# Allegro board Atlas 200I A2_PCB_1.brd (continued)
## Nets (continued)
GND: C4.2 C5.2 C7.2 C8.2 C9.1 C10.1 C11.1 C12.1 C13.1 C14.1 C15.1 C16.1 C17.1 C18.1 C19.2 C20.1 C23.2 C24.2 C27.2 C28.2 C29.2 C30.2 C31.2 C32.1 C33.2 C34.2 C35.2 C36.1 C37.1 C38.1 C39.1 C40.1 C43.1 C44.2 C45.1 C46.2 C47.1 C48.1 C49.1 C50.1 C51.1 C52.1 C53.1 C54.1 C55.1 C56.1 C57.1 C58.1 C59.1 C60.1 C61.1 C62.1 C63.1 C64.2 C65.1 C66.1 C67.1 C68.1 C69.1 C70.1 C71.1 C72.1 C73.1 C74.1 C75.1 C76.1 C77.1 C78.1 C79.1 C80.1 C81.1 C82.1 C85.2 C86.1 C87.1 C88.2 C90.2 C92.2 C93.2 C94.1 C95.2 C98.1 C99.1 C100.1 C101.1 C102.1 C103.1 C104.2 C109.2 C113.1 C115.1 C116.1 C117.1 C118.2 C119.2 C120.1 C121.2 C122.2 C123.1 C124.1 C125.1 C126.1 C127.2 C128.2 C129.1 C130.1 C131.2 C132.2 C133.2 C134.2 C135.2 C136.1 C137.2 C138.1 C139.1 C140.1 C141.2 C142.2 C143.2 C144.2 C145.2 C146.2 C150.2 C151.2 C152.2 C153.2 C154.2 C155.2 C156.2 C157.2 C158.2 C159.2 C160.2 C161.2 C162.2 C163.2 C164.2 C165.2 C166.2 C167.2 C174.2 C175.1 C176.1 C177.1 C178.2 C179.1 C180.2 C181.2 C182.2 C183.2 C184.2 C185.1 C186.1 C187.1 C188.1 C189.2 C190.2 C191.2 C192.2 C193.1 C194.1 C195.1 C196.1 C197.2 C198.2 C199.2 C200.2 C201.2 C202.2 C203.2 C204.2 C205.2 C206.2 C207.2 C208.2 C209.1 C210.1 C212.2 C214.1 C215.2 C216.2 C217.2 C219.2 C220.2 C221.2 C222.1 C223.1 C224.1 C225.1 C227.2 C228.1 C229.1 C230.1 C231.1 C232.1 C233.2 C234.2 C235.2 C236.2 C237.2 C238.2 C241.2 C242.2 C243.2 C244.2 C245.2 C246.2 C247.2 C248.2 C249.2 C252.2 C253.2 C254.2 C255.2 C256.2 C257.2 C258.2 C259.2 C260.2 C261.2 C262.2 C263.2 C264.2 C265.2 C266.2 C267.2 C268.2 C270.2 C271.2 C272.2 C273.2 C274.2 C275.2 C276.2 C277.2 C278.2 C279.2 C280.2 C281.2 C282.2 C283.2 C284.2 C285.1 C286.1 C287.1 C288.2 C289.2 C290.2 C291.2 C292.1 C293.2 C294.2 C295.2 C296.2 C297.2 C298.2 C299.2 C300.1 C301.1 C302.2 C303.1 C304.2 C305.2 C306.2 C307.2 C311.1 C312.2 C313.1 C314.2 C317.2 C318.2 C321.1 C322.1 C323.2 C324.1 C325.1 C326.1 C327.1 C328.2 C329.2 C330.2 C331.2 C332.1 C333.2 C334.2 C335.2 C336.2 C337.2 C338.2 C339.2 C340.2 C341.1 C342.1 C343.2 C344.2 C345.2 C346.1 C347.1 C348.2 C349.2 C350.2 C351.2 C352.2 C353.1 C354.1 C355.1 C356.1 C357.1 C358.1 C359.1 C360.2 C361.2 C362.2 C363.2 C364.1 C365.1 C366.1 C367.2 C368.2 C369.2 C370.2 D2.3 D4.3 D4.8 D5.2 D6.3 D6.8 D9.3 D9.8 D10.3 D10.8 D13.3 D13.8 D15.3 D15.8 D21.3 D21.8 D23.3 D23.8 D30.2 D41.2 F1.1 J1.1 J1.3 J1.9 J1.15 J1.21 J1.27 J1.33 J1.39 J1.45 J1.51 J1.57 J1.71 J1.73 J1.75 J1.76 J1.77 J2.1 J2.7 J2.18 J2.33 J2.39 J2.45 J2.51 J2.57 J2.63 J2.69 J2.75 J2.76 J2.77 J3.6 J3.10 J3.11 J3.12 J3.13 J3.14 J4.1 J4.12 J4.13 J4.24 J4.25 J4.26 J4.27 J4.28 J5.4 J5.7 J5.13 J5.16 J5.19 J5.20 J5.21 J5.22 J6.2 J6.5 J6.8 J6.11 J6.17 J6.20 J6.21 J6.22 J6.23 J7.2 J7.5 J7.8 J7.11 J7.17 J7.20 J7.21 J7.22 J7.23 J8.4 J9.2 J9.3 J10.8 J10.11 J10.14 J10.17 J10.20 J10.23 J10.26 J10.29 J10.32 J10.35 J10.38 J10.41 J10.44 J11.6 J11.9 J11.14 J11.20 J11.25 J11.30 J11.34 J11.39 J16.1 J16.7 J16.12 J16.13 J16.19 J16.25 J16.30 J16.31 J16.36 J16.37 J16.42 J16.43 J16.48 J16.49 J16.54 J16.55 J16.60 J16.61 J16.66 J16.67 J16.72 J16.73 J16.78 J16.79 J16.84 J16.85 J16.90 J16.91 J16.96 J16.97 J16.102 J16.103 J16.108 J16.109 J16.140 J16.151 J16.154 J16.168 J16.171 J16.176 J16.183 J16.190 J16.195 J16.204 J16.210 J16.216 J16.222 J16.223 J16.228 J16.234 J16.240 J16.241 J16.246 J16.252 J16.253 J16.258 J16.264 J16.265 J16.266 J16.267 J16.268 J16.269 J16.270 J16.271 J16.285 J16.298 J16.308 J16.311 J16.322 J16.323 J17.17 J17.25 J17.26 J17.27 J17.28 M1.1 M2.1 M3.1 M4.1 M5.1 M6.1 M7.1 M8.1 M10.1 M11.1 M12.1 OSC1.2 Q1.2 Q4.2 Q5.2 Q6.2 Q8.2 Q10.2 Q12.2 Q13.2 Q14.2 Q15.2 Q16.2 R8.2 R9.2 R10.1 R17.1 R18.1 R25.2 R26.2 R27.2 R28.2 R35.1 R89.2 R91.1 R100.2 R102.2 R103.2 R104.2 R114.1 R117.2 R120.2 R121.2 R122.2 R123.2 R125.2 R127.2 R138.2 R139.2 R140.2 R141.2 R143.2 R144.2 R145.2 R146.2 R164.2 R165.2 R166.2 R167.2 R169.1 R170.1 R173.1 R176.2 R177.2 R178.2 R179.2 R180.2 R181.2 R193.2 R195.2 R200.1 R201.1 R213.1 R216.2 R217.1 R222.2 R223.2 R235.1 R241.2 R242.1 R243.2 R246.1 R248.1 R250.1 R257.2 R272.2 R275.2 R278.1 R279.1 R287.1 R305.1 R307.1 R309.2 R315.1 R317.2 R318.2 R319.1 R320.1 R321.1 R329.2 R330.2 R333.2 R334.2 R335.2 R336.2 R337.2 R338.2 R341.1 R345.1 R348.1 R350.2 R352.1 R358.1 R369.2 R375.2 R376.1 R377.1 R379.1 R383.2 R387.1 R390.1 R393.1 R395.2 R398.1 R400.1 R402.2 R403.2 R405.1 R408.2 R409.2 R412.2 R413.1 R417.1 R420.2 R421.1 R459.1 R470.2 R471.2 R472.2 R486.2 R487.2 R488.2 R516.1 R517.1 R518.1 R519.1 R520.1 R521.1 R522.1 R523.1 R524.1 R525.1 R526.1 R527.1 R528.1 R529.1 R530.1 R531.1 R535.1 R536.1 R537.1 R548.1 R554.1 R573.1 R574.2 R631.2 R633.1 R650.1 S1.3 S1.4 S1.5 S2.3 S2.4 S2.5 S3.3 S3.4 S3.5 TP8.1 TP9.1 U1.49 U2.49 U3.2 U4.2 U5.5 U5.11 U5.20 U5.21 U6.2 U7.4 U8.5 U8.7 U9.5 U9.7 U10.13 U10.18 U10.24 U10.37 U10.43 U10.48 U10.49 U11.2 U12.5 U13.2 U13.3 U13.15 U14.3 U15.8 U15.18 U15.21 U16.2 U17.4 U17.9 U18.4 U19.12 U20.7 U21.7 U22.4 U23.4 U24.7 U25.7 U27.A6 U27.C4 U27.D3 U27.E7 U27.G5 U27.H10 U27.J5 U27.K8 U27.N1 U27.N2 U27.N5 U27.P4 U27.P6 U28.2 U29.2 U30.5 U31.2 U32.7 U33.7 U34.7 U35.7 U36.51 U36.61 U36.77 U37.4 U38.77 VCXO1.2 X1.2 X1.4 X2.2 X2.4 X3.2 X3.4 X4.2 X4.4
VBUS_USB_TYPEC: J4.4 J4.9 J4.16 J4.21 LB7.1 U6.5
/CLKREQ_M2: J1.52 R26.1 R34.1
/CLKREQ_WIFI: J16.319 R42.2 R70.1
/EMMC_RESET: J16.203 R77.1 R79.1 R202.2
/EMMC_RESET_R: C87.2 R77.2 U27.K5
/LED_PHY0_ACT: R98.2 R140.1 R365.2 U1.37
/LED_PHY0_LINK: R99.2 R138.1 R366.2 U1.35
/LED_PHY1_ACT: R146.1 R154.2 R367.2 U2.37
/LED_PHY1_LINK: R144.1 R155.2 R368.2 U2.35
/OC0_USB30_REAR_1: R545.1 R598.1 U38.25
/OC0_USB30_REAR_2: R645.1 R646.1 U38.18
/OC1_USB30_REAR_1: R544.1 R546.2 U36.67
/OC1_USB30_REAR_2: R643.2 R644.1 U36.10
/OC_USB30_REAR_1: R544.2 R545.2 R647.1 U8.3
/OC_USB30_REAR_2: R644.2 R645.2 R648.1 U9.3
/PERST_M2: J16.296 R12.2 R678.1
/PERST_M2_R: C34.1 R23.2 R27.1 R32.1 U21.13
/PERST_WIFI: J16.294 R566.2 R626.1
/PERST_WIFI_R: J2.52 R39.1 R618.2
/PEWAKE_M2: J1.54 R28.1 R33.1
/PEWAKE_WIFI: J16.317 R571.2 R625.1
/PEWAKE_WIFI_R: R41.2 R43.1 R617.2
/RST_USB_HUB_R: C367.1 R632.2 R633.2 R639.2 U38.24
/SDIO_RESET_R: J2.23 R79.2
/SDIO_WAKE_R: J2.21 J16.121 R80.2
/WAKE_PHY0: J16.141 R217.2 R569.2 R624.1
/WAKE_PHY0_R: R101.1 R124.2 R125.1 R616.2
/WAKE_PHY1: J16.321 R235.2 R565.2 R621.1
/WAKE_PHY1_R: R168.1 R192.2 R193.1 R613.2
/WAKE_UART3: R44.2 R48.1
AC_IN_L: C149.1 J16.306 LB12.2
AC_IN_R: C148.1 J16.304 LB11.2
AC_MICBIAS0: J16.300 R314.2
BOARD_ID0: R507.1 R523.2 U19.4
BOARD_ID1: R506.1 R522.2 U19.5
BOARD_ID2: R505.1 R521.2 U19.6
BOARD_ID3: R504.1 R520.2 U19.7
BOARD_ID4: R503.1 R519.2 U19.8
BOARD_ID5: R502.1 R518.2 U19.9
BOARD_ID6: R501.1 R517.2 U19.10
BOARD_ID7: R500.1 R516.2 U19.11
BOM_ID0: R508.1 R524.2 U19.13
BOM_ID1: R509.1 R525.2 U19.14
BOM_ID2: R510.1 R526.2 U19.15
BOOT_SEL0: J16.137 SW1.2
BOOT_SEL1: J16.135 SW1.3
BOOT_SEL2: J16.133 SW1.4
BPWR_DET_USB2: R460.2 R632.1 U36.2
BPWR_VL817_HUB1: R577.1 U38.45
CARD_DETECT: J3.9 R234.2 U4.6(TP-6)
CFG_PHY0_LDO0: R97.2 R139.1 U1.36
CFG_PHY1_LDO0: R145.1 R153.2 U2.36
CLK_100M_BUF_M2_L1_N: R327.1 U10.7
CLK_100M_BUF_M2_L1_P: R328.1 U10.6
CLK_100M_BUF_M2_N: C173.2 J1.53 R13.1
CLK_100M_BUF_M2_P: C172.2 J1.55 R13.2
CLK_100M_BUF_SLOT_L1_N: R325.1 U10.2
CLK_100M_BUF_SLOT_L1_P: R326.1 U10.1
CLK_100M_BUF_WIFI_L1_N: R324.1 U10.12
CLK_100M_BUF_WIFI_L1_P: R323.1 U10.11
CLK_100M_BUF_WIFI_N: C168.2 J2.49 R40.2
CLK_100M_BUF_WIFI_P: C169.2 J2.47 R40.1
CLK_100M_M2_L2_N: C173.1 R327.2 R335.1
CLK_100M_M2_L2_P: C172.1 R328.2 R336.1
CLK_100M_OSC: C95.1 R3.2 R340.1 R344.2 R345.2 U10.20
CLK_100M_SLOT1_L2_N: C171.1 R325.2 R337.1
CLK_100M_SLOT1_L2_P: C170.1 R326.2 R338.1
CLK_100M_WIFI_L2_N: C168.1 R324.2 R333.1
CLK_100M_WIFI_L2_P: C169.1 R323.2 R334.1
CLKIN_SEL0: R330.1 U10.19
CLKIN_SEL1: R329.1 U10.22
CLKOUTA_TYPE0: R316.2 R317.1 U10.14
CLKOUTA_TYPE1: R318.1 R322.2 U10.47
DEVSLP_M2: R22.2 R24.1 R25.1
DSI_I2C_INT: J16.227 R627.1
DSI_I2C_INT_R: R425.1 U25.13
EMMC_CLK: J16.199 R71.1 R86.1 R216.1
EMMC_CLK_R: C86.2 R71.2 U27.M6
EMMC_CMD: J16.201 R72.1 R85.1 R203.2
EMMC_CMD_R: R72.2 U27.M5
EMMC_DATA0: J16.207 R73.1 R84.1 R208.2
EMMC_DATA0_R: R73.2 U27.A3
EMMC_DATA1: J16.209 R74.1 R83.1 R209.2
EMMC_DATA1_R: R74.2 U27.A4
EMMC_DATA2: J16.211 R75.1 R82.1 R210.2
EMMC_DATA2_R: R75.2 U27.A5
EMMC_DATA3: J16.213 R76.1 R81.1 R211.2
EMMC_DATA3_R: R76.2 U27.A1 U27.B2
EMMC_DATA4: J16.215 R37.1 R207.2 R218.1
EMMC_DATA4_R: R218.2 U27.A2 U27.B3
EMMC_DATA5: J16.217 R37.2 R206.2 R219.1
EMMC_DATA5_R: R219.2 U27.B4 U27.C3 U27.D2 U27.E3 U27.F3
EMMC_DATA6: J16.219 R38.1 R205.2 R220.1
EMMC_DATA6_R: R220.2 U27.B5 U27.C5
EMMC_DATA7: J16.221 R38.2 R204.2 R221.1
EMMC_DATA7_R: R221.2 U27.A8 U27.B6 U27.B7
EMMC_DS: J16.205 R78.1 R222.1
EMMC_DS_R: R78.2 U27.H5
EMMC_POWER_EN: J16.197 R2.1 R212.1
FAN_PWM0: C309.1 J16.288 R348.2 R354.1
FAN_PWM_CTRL: J8.2 Q10.3 R352.2 R353.1
FAN_STA: C184.1 J16.284 R346.1
GATE_24711: C213.1 R381.1 U12.7
GPIO13: J16.314 R5.1
GPIO13_3V3: R56.2 U21.11
GPIO16: J16.149 R292.1 R635.1
GPIO16_3V3: R64.2 R258.1 U20.13
GPIO17: J16.147 R237.1 R293.1
GPIO17_3V3: R65.2 R447.2 U20.12
GPIO22: J16.20 R294.1 R575.1
GPIO22_3V3: R236.2 R448.2 U20.11
GPIO23: J16.18 R295.1 R637.1
GPIO23_3V3: R238.2 R435.1 U20.10
GPIO24: J16.282 R636.1
GPIO24_3V3: R440.1 U32.13
GPIO25: J16.292 R674.1
GPIO25_3V3: R289.1 U32.12
GPIO26: J16.290 R669.1
GPIO26_3V3: R452.2 U32.11
GPIO27: J16.191 R6.1
GPIO27_3V3: R57.2 U21.10
HDMI0_CEC: J16.239 R280.2 R281.1
HDMI0_HOTPLUG: C142.1 J16.237 R285.1 R286.2 R287.2
HDMI0_SCL: J16.230 R282.1 R296.2
HDMI0_SDA: J16.232 R283.1 R284.2
HDMI0_TX0_C_N: D15.4 D15.7 J6.9 R256.2
HDMI0_TX0_C_P: D15.5 D15.6 J6.7 R255.2
HDMI0_TX0_N: J16.220 R256.1
HDMI0_TX0_P: J16.218 R255.1
HDMI0_TX1_C_N: D13.1 D13.10 J6.6 R310.2
HDMI0_TX1_C_P: D13.2 D13.9 J6.4 R311.2
HDMI0_TX1_N: J16.214 R310.1
HDMI0_TX1_P: J16.212 R311.1
HDMI0_TX2_C_N: D13.4 D13.7 J6.3 R312.2
HDMI0_TX2_C_P: D13.5 D13.6 J6.1 R313.2
HDMI0_TX2_N: J16.208 R312.1
HDMI0_TX2_P: J16.206 R313.1
HDMI0_TX_5V: C141.1 D17.3 J6.18 R284.1 R285.2 R296.1 U28.5
HDMI0_TX_CEC: J6.13 R281.2 U28.4
HDMI0_TX_DDC_SCL_C: J6.15 R282.2 U28.6(TP-6)
HDMI0_TX_DDC_SDA_C: J6.16 R283.2 U28.3
HDMI0_TX_HPD_C: J6.19 R286.1 U28.1
HDMI0_TXC_C_N: D15.1 D15.10 J6.12 R331.2
HDMI0_TXC_C_P: D15.2 D15.9 J6.10 R332.2
HDMI0_TXC_N: J16.226 R331.1
HDMI0_TXC_P: J16.224 R332.1
HDMI1_CEC: J16.235 R298.2 R299.1
HDMI1_HOTPLUG: C145.1 J16.233 R303.1 R304.2 R305.2
HDMI1_SCL: J16.27 R297.2 R300.1
HDMI1_SDA: J16.29 R301.1 R302.2
HDMI1_TX0_C_N: D23.4 D23.7 J7.9 R364.2
HDMI1_TX0_C_P: D23.5 D23.6 J7.7 R397.2
HDMI1_TX0_N: J16.17 R364.1
HDMI1_TX0_P: J16.15 R397.1
HDMI1_TX1_C_N: D21.1 D21.10 J7.6 R360.2
HDMI1_TX1_C_P: D21.2 D21.9 J7.4 R361.2
HDMI1_TX1_N: J16.11 R360.1
HDMI1_TX1_P: J16.9 R361.1
HDMI1_TX2_C_N: D21.4 D21.7 J7.3 R349.2
HDMI1_TX2_C_P: D21.5 D21.6 J7.1 R359.2
HDMI1_TX2_N: J16.5 R349.1
HDMI1_TX2_P: J16.3 R359.1
HDMI1_TX_5V: C144.1 D25.3 J7.18 R297.1 R302.1 R303.2 U29.5
HDMI1_TX_CEC: J7.13 R299.2 U29.3
HDMI1_TX_DDC_SCL_C: J7.15 R300.2 U29.6(TP-6)
HDMI1_TX_DDC_SDA_C: J7.16 R301.2 U29.4
HDMI1_TX_HPD_C: J7.19 R304.1 U29.1
HDMI1_TXC_C_N: D23.1 D23.10 J7.12 R339.2
HDMI1_TXC_C_P: D23.2 D23.9 J7.10 R343.2
HDMI1_TXC_N: J16.23 R339.1
HDMI1_TXC_P: J16.21 R343.1
HDMI_TX_3V3: C143.1 C146.1 D18.3 R280.1 R298.1
HOT_RST_FAULT: J16.295 R479.2
HUB_1V2_LX: L7.1 U38.39
HUB_1V2_SWR: L6.1 U36.52
HUB_3V3_LX: LB20.1 R606.1 U38.21
I2C6_SCL: J16.6 R61.2 R442.1
I2C6_SDA: J16.4 R60.2 R449.2
I2C7_SCL: J16.2 R595.1 R601.2
I2C7_SCL_HUB0: R597.1 U38.36
I2C7_SCL_HUB1: R592.1 U36.34
I2C7_SCL_R: R445.2 R592.2 R597.2 R599.1 U22.7
I2C7_SDA: J16.320 R596.1 R602.2
I2C7_SDA_HUB0: R593.1 U38.37
I2C7_SDA_HUB1: R590.1 U36.35
I2C7_SDA_R: R444.2 R590.2 R593.2 R600.1 U22.6
I2C8_SCL: J16.318 R58.2 R490.1 R496.2
I2C8_SCL_R: R482.2 R493.2 R494.1 R499.2
I2C8_SDA: J16.316 R59.2 R491.1 R497.2
I2C8_SDA_R: R481.2 R492.2 R495.1 R498.2
I2S0_BCLK: J16.261 R53.1
I2S0_BCLK_R: R454.1 U35.13
I2S0_LRCK: J16.259 R557.1
I2S0_LRCK_R: R453.2 U35.12
I2S0_MCLK: J16.263 R671.1
I2S0_MCLK_R: R288.2 U33.13
I2S0_MISO: J16.255 R572.1
I2S0_MISO_R: R455.1 U35.11
I2S0_MOSI: J16.257 R556.1
I2S0_MOSI_R: R456.1 U35.10
I2S1_BCLK: J16.249 R55.2
I2S1_LRCK: J16.247 R45.2
I2S1_MCLK: J16.251 R612.1
I2S1_MCLK_R: R450.2 U33.12
I2S1_MISO: J16.243 R62.2
I2S1_MOSI: J16.245 R63.2
LED_G: Q15.3 R419.1
LED_HEALTHY_G: Q13.3 R411.1
LED_HEALTHY_R: Q12.3 R410.1
LED_R: Q14.3 R418.1
LSADC0: J16.312 R8.1
LSADC1: J16.310 R9.1
M2_TYPE: J16.315 R15.2 R16.1 R17.2
MDI_PHY0_0_N: D33.1 D33.8(TP-8) R137.2 T19.12
MDI_PHY0_0_P: D33.2 D33.7 R136.2 T19.11
MDI_PHY0_1_N: D33.3 D33.6 R130.2 T19.9
MDI_PHY0_1_P: D33.4 D33.5 R131.2 T19.8
MDI_PHY0_2_N: D34.1 D34.8(TP-8) R132.2 T19.6
MDI_PHY0_2_P: D34.2 D34.7 R133.2 T19.5
MDI_PHY0_3_N: D34.4 D34.5 R134.2 T19.3
MDI_PHY0_3_P: D34.3 D34.6 R135.2 T19.2
MDI_PHY1_0_N: D43.1 D43.8(TP-8) R191.2 T20.12
MDI_PHY1_0_P: D43.2 D43.7 R190.2 T20.11
MDI_PHY1_1_N: D43.3 D43.6 R184.2 T20.9
MDI_PHY1_1_P: D43.4 D43.5 R185.2 T20.8
MDI_PHY1_2_N: D40.1 D40.8(TP-8) R186.2 T20.6
MDI_PHY1_2_P: D40.2 D40.7 R187.2 T20.5
MDI_PHY1_3_N: D40.3 D40.6 R188.2 T20.3
MDI_PHY1_3_P: D40.4 D40.5 R189.2 T20.2
MIPI_DSI_CK_N: J10.25 J16.262
MIPI_DSI_CK_P: J10.27 J16.260
MIPI_DSI_D0_N: J10.34 J16.238
MIPI_DSI_D0_P: J10.36 J16.236
MIPI_DSI_D1_N: J10.22 J16.244
MIPI_DSI_D1_P: J10.24 J16.242
MIPI_DSI_D2_N: J10.28 J16.250
MIPI_DSI_D2_P: J10.30 J16.248
MIPI_DSI_D3_N: J10.31 J16.256
MIPI_DSI_D3_P: J10.33 J16.254
MIPI_DSI_SCL: J16.231 R604.1 R610.2
MIPI_DSI_SCL_R: R428.1 R608.1 U23.7
MIPI_DSI_SDA: J16.229 R605.1 R611.2
MIPI_DSI_SDA_R: R427.2 R609.1 U23.6
MIPI_GPIO: J16.225 R638.1
MIPI_GPIO_R: R426.2 U32.10
PCA9555A_A0: R532.1 R537.2 U19.21
PCA9555A_A1: R533.1 R536.2 U19.2
PCA9555A_A2: R534.1 R535.2 U19.3
PCB_ID0: R511.1 R527.2 U19.16
PCB_ID1: R512.1 R528.2 U19.17
PCB_ID2: R513.1 R529.2 U19.18
PCIE_EP_RC_FLAG: J16.313 R35.2
PCIE_RX_N/SATA_B_P: J1.41 R30.2
PCIE_RX_P/SATA_B_N: J1.43 R31.2
PCIE_TX_N/SATA_A_N: C6.2 J1.47
PCIE_TX_P/SATA_A_P: C1.2 J1.49
PHY0_MDI0_N: J17.2 T19.13
PHY0_MDI0_P: J17.1 T19.14
PHY0_MDI1_N: J17.6 T19.16
PHY0_MDI1_P: J17.3 T19.17
PHY0_MDI2_N: J17.5 T19.19
PHY0_MDI2_P: J17.4 T19.20
PHY0_MDI3_N: J17.8 T19.22
PHY0_MDI3_P: J17.7 T19.23
PHY1_MDI0_N: J17.10 T20.13
PHY1_MDI0_P: J17.9 T20.14
PHY1_MDI1_N: J17.14 T20.16
PHY1_MDI1_P: J17.11 T20.17
PHY1_MDI2_N: J17.13 T20.19
PHY1_MDI2_P: J17.12 T20.20
PHY1_MDI3_N: J17.16 T20.22
PHY1_MDI3_P: J17.15 T20.23
POWER_EN: J16.301 R480.1 U16.1
PWM1: J16.286 R676.1
PWM1_R: R443.1 U21.12
RGMII0_MDCK: J16.170 R117.1 R118.2 R129.1
RGMII0_MDIO: J16.172 R119.2 R128.1
RGMII0_RST: J16.174 R173.2 R568.2 R623.1
RGMII0_RST_R: C264.1 R126.2 R127.1 R615.2 U1.13
RGMII0_RXCK: J16.202 R111.2
RGMII0_RXD0: J16.198 R107.2
RGMII0_RXD1: J16.196 R108.2
RGMII0_RXD2: J16.194 R109.2
RGMII0_RXD3: J16.192 R110.2
RGMII0_RXDV: J16.200 R112.2
RGMII0_TXCK: C121.1 J16.188 U1.21
RGMII0_TXD0: C128.1 J16.184 U1.19
RGMII0_TXD1: C135.1 J16.182 U1.18
RGMII0_TXD2: C150.1 J16.180 U1.17
RGMII0_TXD3: C151.1 J16.178 U1.16
RGMII0_TXEN: C122.1 J16.186 U1.20
RGMII1_MDCK: J16.134 R175.2 R176.1 R183.1
RGMII1_MDIO: J16.136 R174.2 R182.1
RGMII1_RST: J16.138 R200.2 R564.2 R622.1
RGMII1_RST_R: C265.1 R194.2 R195.1 R614.2 U2.13
RGMII1_RXCK: J16.166 R159.2
RGMII1_RXD0: J16.162 R163.2
RGMII1_RXD1: J16.160 R162.2
RGMII1_RXD2: J16.158 R161.2
RGMII1_RXD3: J16.156 R160.2
RGMII1_RXDV: J16.164 R158.2
RGMII1_TXCK: C154.1 J16.152 U2.21
RGMII1_TXD0: C160.1 J16.148 U2.19
RGMII1_TXD1: C166.1 J16.146 U2.18
RGMII1_TXD2: C174.1 J16.144 U2.17
RGMII1_TXD3: C178.1 J16.142 U2.16
RGMII1_TXEN: C159.1 J16.150 U2.20
RGMII_CLK_PHY0: C109.1 R96.2 R100.1 R111.1 U1.28
RGMII_CLK_PHY1: C44.1 R152.2 R159.1 R177.1 U2.28
RGMII_DV_PHY0: R92.2 R112.1 R120.1 U1.27
RGMII_DV_PHY1: R148.2 R158.1 R181.1 U2.27
RGMII_PHY0_D0: R90.2 R107.1 R141.1 U1.26
RGMII_PHY0_D1: R93.2 R108.1 R123.1 U1.25
RGMII_PHY0_D2: R94.2 R109.1 R122.1 U1.24
RGMII_PHY0_D3: R95.2 R110.1 R121.1 U1.23
RGMII_PHY1_D0: R143.1 R147.2 R163.1 U2.26
RGMII_PHY1_D1: R149.2 R162.1 R180.1 U2.25
RGMII_PHY1_D2: R150.2 R161.1 R179.1 U2.24
RGMII_PHY1_D3: R151.2 R160.1 R178.1 U2.23
SD_CLK: J3.5 R171.2 U3.4
SD_CMD: J3.3 R226.2 U3.6(TP-6)
SD_DATA0: J3.7 R227.2 U4.1
SD_DATA1: J3.8 R228.2 U4.3
SD_DATA2: J3.1 R224.2 U3.1
SD_DATA3: J3.2 R225.2 U3.3
SDIO_CLK: J16.169 R171.1 R308.2 R309.1
SDIO_CLK_R: J2.9 R86.2
SDIO_CMD: J16.167 R226.1 R233.2
SDIO_CMD_R: J2.11 R85.2
SDIO_DATA0: J16.165 R227.1 R232.2
SDIO_DATA0_R: J2.13 R84.2
SDIO_DATA1: J16.163 R228.1 R231.2
SDIO_DATA1_R: J2.15 R83.2
SDIO_DATA2: J16.161 R224.1 R230.2
SDIO_DATA2_R: J2.17 R82.2
SDIO_DATA3: J16.159 R225.1 R229.2
SDIO_DATA3_R: J2.19 R81.2
SDIO_DETECT: C104.1 J16.155 R223.1 R234.1 R240.2
SDIO_POWER_EN: J16.157 R1.1
SDIO_VOUT: J16.153 R229.1 R230.1 R231.1 R232.1 R233.1 R240.1 R308.1
SERDES0_RX_N: J16.38 R30.1
SERDES0_RX_P: J16.40 R31.1
SERDES0_TX_N: C6.1 J16.39
SERDES0_TX_P: C1.1 J16.41
SERDES1_RX_N: J1.29 J16.44
SERDES1_RX_P: J1.31 J16.46
SERDES1_TX_N: C3.1 J16.45
SERDES1_TX_P: C2.1 J16.47
SERDES2_RX_N: J1.17 J16.50
SERDES2_RX_P: J1.19 J16.52
SERDES2_TX_N: C25.1 J16.51
SERDES2_TX_P: C26.1 J16.53
SERDES3_RX_N: J1.5 J16.56
SERDES3_RX_P: J1.7 J16.58
SERDES3_TX_N: C21.1 J16.57
SERDES3_TX_P: C22.1 J16.59
SERDES4_RX_N: J2.43 J16.86
SERDES4_RX_P: J2.41 J16.88
SERDES4_TX_N: C42.1 J16.87
SERDES4_TX_P: C41.1 J16.89
SERDES_CLK0_N: C171.2 J16.32
SERDES_CLK0_P: C170.2 J16.34
SPI0_CLK: J16.189 R88.2 R405.2 R641.1
SPI0_CLK_R: R437.1 U34.10
SPI0_CS0: J16.193 R634.1
SPI0_CS0_R: R436.1 U34.13
SPI0_MISO: J16.185 R670.1
SPI0_MISO_R: R438.1 U34.11
SPI0_MOSI: J16.187 R87.2 R400.2 R620.1
SPI0_MOSI_R: R439.1 U34.12
SPI2_CLK: J16.177 R413.2 R414.1
SPI2_CS0: J16.181 R412.1 R415.1
SPI2_MISO: J16.173 R420.1 R423.1
SPI2_MOSI: J16.175 R421.2 R422.1
SPI_CLK_HUB0: R587.1 U38.34
SPI_CS_HUB: R563.2 R584.2 R588.2 R630.1 R631.1
SPI_CS_HUB0: R588.1 U38.32
SPI_CS_HUB1: R584.1 U36.45
SPI_MISO_HUB: R562.1 R581.2 R585.2
SPI_MISO_HUB0: R585.1 U38.33
SPI_MISO_HUB1: R581.1 U36.46
SPI_MOSI_HUB: R567.1 R582.2 R586.2
SPI_MOSI_HUB0: R586.1 U38.35
SPI_MOSI_HUB1: R582.1 U36.47
SPI_SCK_HUB: R561.2 R583.2 R587.2
SPI_SCK_HUB1: R583.1 U36.44
SPWR_DET_REAR_HUB1: R576.1 U38.44
SPWR_DET_USB2: R467.2 U36.76
SYS_RST_IN: J16.297 R463.1
SYS_RST_IN_R: C286.2 R463.2 R464.1 S3.1 S3.2
TAISHAN_POWEROFF_IN: J16.299 R465.1
TAISHAN_POWEROFF_IN_R: C287.2 R465.2 R466.1 S2.1 S2.2
TAISHAN_SLEEP_IN: J16.291 SW1.1
TAISHAN_SLEEP_OUT: J16.289 R291.1
TAISHAN_SLEEP_OUT_R: R290.1 U24.11
TYPE_ID0: R514.1 R530.2 U19.19
TYPE_ID1: R515.1 R531.2 U19.20
TYPEC_CC1: C120.2 J4.5 R246.2 U6.3 U7.2
TYPEC_CC2: J4.17 U6.4
UART0_RX: J16.14 R253.1 R704.2
UART0_RX_R: R113.1 R433.1 U30.3
UART0_TX: J16.16 R252.1 R703.2
UART0_TX_R: R36.1 R51.1 U30.2
UART2_CTX: J16.143 R7.1
UART2_CTX_R: R21.2 U33.11
UART2_RTX: J16.145 R19.1
UART2_RTX_R: R29.1 U33.10
UART3_CTX: J16.22 R46.2 R50.1
UART3_RTX: J16.24 R67.1 R69.2
UART3_RX: J16.26 R47.2 R49.1
UART3_TX: J16.28 R66.1 R68.2
UHT_ALARM: J16.303 R54.1
UPDATE_MODE: J16.139 R461.1
UPDATE_MODE_R: C285.2 R461.2 R462.1 S1.1 S1.2
USB0_5V0: C4.1 C5.1 C7.1 C8.1 C23.1 C127.1 D2.1 J5.1 LB9.2 R278.2
USB1_5V0: C24.1 C27.1 C28.1 C30.1 C31.1 C134.1 D2.2 J5.10 LB10.2 R279.2
USB2_1_CONN_DN: J5.2 R260.2 T5.3 U31.1
USB2_1_CONN_DP: J5.3 R261.2 T5.2 U31.3
USB2_1_DN: J16.123 T21.1
USB2_1_DP: J16.125 T21.4(TP-4)
USB2_2_CONN_DN: J5.11 R266.2 T8.3 U31.6(TP-6)
USB2_2_CONN_DP: J5.12 R267.2 T8.2 U31.4
USB2_2_DN: J16.116 R424.1
USB2_2_DP: J16.118 R416.1
USB2_3_DN: J16.117 R474.2 R475.2
USB2_3_DP: J16.119 R468.2 R473.2
USB2_3_HUB0_DN: R474.1 U38.54
USB2_3_HUB0_DP: R468.1 U38.53
USB2_3_HUB1_DN: R475.1 U36.57
USB2_3_HUB1_DP: R473.1 U36.56
USB3_1_CONN_RX_N: D9.1 D9.10 J5.5 R263.2 T6.3
USB3_1_CONN_RX_P: D9.2 D9.9 J5.6 R262.2 T6.2
USB3_1_CONN_TX_N: D10.1 D10.10 J5.8 R264.2 T7.3
USB3_1_CONN_TX_P: D10.2 D10.9 J5.9 R265.2 T7.2
USB3_1_RX_N: J16.92 U5.8
USB3_1_RX_P: J16.94 U5.7
USB3_1_TX_N: C310.2 J16.93
USB3_1_TX_P: C308.2 J16.95
USB3_2_CONN_RX_N: D9.4 D9.7 J5.14 R269.2 T9.3
USB3_2_CONN_RX_P: D9.5 D9.6 J5.15 R268.2 T9.2
USB3_2_CONN_TX_N: D10.4 D10.7 J5.17 R270.2 T10.3
USB3_2_CONN_TX_P: D10.5 D10.6 J5.18 R271.2 T10.2
USB3_2_RX_N: J16.98
USB3_2_RX_P: J16.100
USB3_2_TX_N: J16.99
USB3_2_TX_P: J16.101
USB3_3_RX_HUB0_N: C108.2 U38.47
USB3_3_RX_HUB0_P: C107.2 U38.48
USB3_3_RX_HUB1_N: C105.2 U36.59
USB3_3_RX_HUB1_P: C106.2 U36.60
USB3_3_RX_N: C105.1 C108.1 J16.104
USB3_3_RX_P: C106.1 C107.1 J16.106
USB3_3_TX_HUB0_N: C111.2 U38.50
USB3_3_TX_HUB0_P: C110.2 U38.51
USB3_3_TX_HUB1_N: C96.2 U36.62
USB3_3_TX_HUB1_P: C97.2 U36.63
USB3_3_TX_N: C96.1 C111.1 J16.105
USB3_3_TX_P: C97.1 C110.1 J16.107
USB3_3_TYPEA1_HUB0_RX1_N: R432.1 U38.5
USB3_3_TYPEA1_HUB0_RX1_P: R430.1 U38.4
USB3_3_TYPEA1_HUB0_TX1_N: C372.1 U38.2
USB3_3_TYPEA1_HUB0_TX1_P: C112.1 U38.1
USB3_3_TYPEA1_HUB1_RX1_N: R431.1 U36.69
USB3_3_TYPEA1_HUB1_RX1_P: R429.1 U36.68
USB3_3_TYPEA1_HUB1_TX1_N: C371.1 U36.66
USB3_3_TYPEA1_HUB1_TX1_P: C114.1 U36.65
USB3_3_TYPEA1_HUB_RX1_N: R263.1 R431.2 R432.2 T6.4(TP-4)
USB3_3_TYPEA1_HUB_RX1_P: R262.1 R429.2 R430.2 T6.1
USB3_3_TYPEA1_HUB_TX1_N: C371.2 C372.2 R264.1 T7.4(TP-4)
USB3_3_TYPEA1_HUB_TX1_P: C112.2 C114.2 R265.1 T7.1
USB3_3_TYPEA2_HUB0_RX2_N: R451.1 U38.72
USB3_3_TYPEA2_HUB0_RX2_P: R441.1 U38.71
USB3_3_TYPEA2_HUB0_TX2_N: C376.1 U38.69
USB3_3_TYPEA2_HUB0_TX2_P: C374.1 U38.68
USB3_3_TYPEA2_HUB1_RX2_N: R446.1 U36.12
USB3_3_TYPEA2_HUB1_RX2_P: R434.1 U36.11
USB3_3_TYPEA2_HUB1_TX2_N: C375.1 U36.9
USB3_3_TYPEA2_HUB1_TX2_P: C373.1 U36.8
USB3_3_TYPEA2_HUB_RX2_N: R269.1 R446.2 R451.2 T9.4(TP-4)
USB3_3_TYPEA2_HUB_RX2_P: R268.1 R434.2 R441.2 T9.1
USB3_3_TYPEA2_HUB_TX2_N: C375.2 C376.2 R270.1 T10.4(TP-4)
USB3_3_TYPEA2_HUB_TX2_P: C373.2 C374.2 R271.1 T10.1
USB3_CON_RX1_N: T3.4 U5.12
USB3_CON_RX1_P: T3.1 U5.13
USB3_CON_RX2_N: T4.4 U5.16
USB3_CON_RX2_P: T4.1 U5.17
USB3_CON_TX1_N: T2.4 U5.14
USB3_CON_TX1_P: T2.1 U5.15
USB3_CON_TX2_N: T1.4 U5.18
USB3_CON_TX2_P: T1.1 U5.19
USB3_SSRX1_N: D4.5 D4.6 J4.22 T3.3
USB3_SSRX1_P: D4.4 D4.7 J4.23 T3.2
USB3_SSRX2_N: D6.5 D6.6 J4.10 T4.3
USB3_SSRX2_P: D6.4 D6.7 J4.11 T4.2
USB3_SSTX1_N: D4.2 D4.9 J4.3 T2.3
USB3_SSTX1_P: D4.1 D4.10 J4.2 T2.2
USB3_SSTX2_N: D6.2 D6.9 J4.15 T1.3
USB3_SSTX2_P: D6.1 D6.10 J4.14 T1.2
USB3_SW_SEL: R243.1 R259.2 U5.9
USB20_TYPEA1_HUB0_DN: R539.1 U38.8
USB20_TYPEA1_HUB0_DP: R477.1 U38.7
USB20_TYPEA1_HUB1_DN: R538.1 U36.72
USB20_TYPEA1_HUB1_DP: R476.1 U36.71
USB20_TYPEA1_HUB_DN: R260.1 R538.2 R539.2 T5.4(TP-4)
USB20_TYPEA1_HUB_DP: R261.1 R476.2 R477.2 T5.1
USB20_TYPEA2_HUB0_DN: R543.1 U38.75
USB20_TYPEA2_HUB0_DP: R541.1 U38.74
USB20_TYPEA2_HUB1_DN: R542.1 U36.6
USB20_TYPEA2_HUB1_DP: R540.1 U36.5
USB20_TYPEA2_HUB_DN: R266.1 R542.2 R543.2 T8.4(TP-4)
USB20_TYPEA2_HUB_DP: R267.1 R540.2 R541.2 T8.1
USB30_PWR0_EN1: R274.2 R549.2 U8.4 U38.26
USB30_PWR0_EN2: R277.2 R555.2 U9.4 U38.19
USB30_PWR1_EN1: C311.2 Q1.1 R547.1 R548.2 R550.1
USB30_PWR1_EN2: C313.2 Q6.1 R458.1 R551.1 R554.2
USB_12M_X0_HUB1: R558.1 U36.75
USB_12M_XI_HUB1: R559.1 U36.74
USB_25M_XI_HUB1: R579.1 U38.55
USB_25M_XO_HUB1: R580.1 U38.56
USB_TYPEC_CON_DN: J4.7 J4.19 T21.2 U6.1
USB_TYPEC_CON_DP: J4.6 J4.18 T21.3 U6.6(TP-6)
USB_VBUS: J16.115 R244.2
USB_VBUS_CON: C116.2 C117.2 C119.1 LB7.2 R14.2 R247.2 R306.1 U7.8
V_3V3_HUB: C318.1 R607.1 R619.1 R630.2 R640.2 R642.2 U37.8
V_3V3_USBHUB0: C180.1 C205.1 C206.1 C207.1 C208.1 C209.2 C210.2 C220.1 LB18.2 R460.1 R467.1 R546.1 R547.2 R551.2 R640.1 R643.1 R649.1 U36.4 U36.22 U36.48 U36.53 U36.54 U36.55 U36.73
V_5V0_HUB: C342.2 C345.1 C346.2 C347.2 C348.1 C349.1 C350.1 C351.1 C352.1 C368.1 LB19.2 U38.20 U38.38
V_12V0_CON_IN: F3.1 J9.1
V_12V0_CON_IN_F: C218.1 C226.1 D35.1 F3.2 R371.2 R372.2 R373.2 R374.2 R382.1 U12.9
V_12V0_SENSE: C211.1 Q11.5 Q11.6 Q11.7 Q11.8 R380.2 R382.2
V_AVDD_1V0_PHY0: C52.2 C53.2 C56.2 LB1.2 U1.4 U1.9 U1.47
V_AVDD_1V0_PHY1: C71.2 C72.2 C73.2 LB4.2 U2.4 U2.9 U2.47
V_AVDD_3V3_PHY0: C49.2 C50.2 C51.2 LB2.2 U1.1 U1.12
V_AVDD_3V3_PHY1: C75.2 C76.2 C77.2 LB5.2 U2.1 U2.12
V_BAT_3V0: D1.3 J16.283
V_DV11_HUB: C323.1 C325.2 C326.2 C328.1 C330.1 C331.1 C334.1 C336.1 C337.1 C339.1 C340.1 C357.2 C358.2 C359.2 C360.1 C361.1 C362.1 C363.1 C364.2 C365.2 C366.2 L7.2 U38.3 U38.9 U38.12 U38.22 U38.40 U38.46 U38.49 U38.61 U38.67 U38.70 U38.76
V_DV12_HUB: C227.1 C245.1 C246.1 C252.1 C253.1 C272.1 C278.1 C279.1 C297.1 C302.1 C305.1 L6.2 U36.3 U36.7 U36.13 U36.19 U36.25 U36.31 U36.49 U36.50 U36.58 U36.64 U36.70
V_DV33_HUB: C324.2 C327.2 C329.1 C332.2 C333.1 C335.1 C338.1 C341.2 C353.2 C354.2 C355.2 C356.2 LB20.2 R576.2 R577.2 R598.2 R606.2 R639.1 R642.1 R646.2 R651.1 R652.2 U38.6 U38.15 U38.29 U38.43 U38.52 U38.58 U38.64 U38.73
V_DVDD_1V0_PHY0: C54.2 C55.2 C57.2 C58.2 L1.1 LB1.1 U1.22
V_DVDD_1V0_PHY1: C66.2 C67.2 C69.2 C70.2 L2.1 LB4.1 U2.22
V_STBY_1V8: C33.1 C36.2 C38.2 C83.2 C131.1 C132.1 C136.2 C138.2 C266.1 C268.1 C292.2 C295.1 C296.1 C298.1 C299.1 C304.1 J2.64 Q2.2 R12.1 R15.1 R20.2 R42.1 R49.2 R50.2 R66.2 R67.2 R80.1 R87.1 R88.1 R116.1 R156.1 R197.2 R239.2 R254.1 R292.2 R293.2 R294.2 R295.2 R347.2 R354.2 R396.2 R398.2 R462.2 R464.2 R466.2 R469.2 R496.1 R497.1 R552.2 R553.2 R564.1 R565.1 R566.1 R568.1 R569.1 R571.1 R589.2 R591.2 R601.1 R602.1 R610.1 R611.1 R628.2 R629.2 R703.1 R704.1 U15.1 U15.19 U15.20 U18.1 U20.1 U21.1 U22.1 U23.1 U24.1 U25.1 U30.8(TP-8) U32.1 U33.1 U34.1 U35.1
V_STBY_3V3: C9.2 C10.2 C11.2 C12.2 C14.2 C16.2 C17.2 C18.2 C19.1 C20.2 C29.1 C37.2 C39.2 C40.2 C43.2 C59.2 C78.2 C84.2 C129.2 C130.2 C133.1 C137.1 C139.2 C140.2 C153.1 C162.1 C164.1 C165.1 C175.2 C176.2 C181.1 C238.1 C247.1 C248.1 C263.1 C267.1 C270.1 C275.1 C282.1 C288.1 C290.1 C291.1 C293.1 C294.1 C300.2 C301.2 C303.2 D3.1 D18.1 J1.2 J1.4 J1.12 J1.14 J1.16 J1.18 J1.70 J1.72 J1.74 J2.2 J2.4 J2.72 J2.74 J10.45 J10.50 J10.51 J11.1 J11.17 L4.2 LB3.1 LB6.1 LB8.2 LB13.1 LB14.1 LB15.1 LB18.1 LED1.1 LED1.2 LED3.1 LED3.2 LED4.1 LED4.2 Q3.2 R24.2 R32.2 R33.2 R34.2 R36.2 R39.2 R41.1 R48.2 R60.1 R61.1 R64.1 R65.1 R113.2 R199.2 R236.1 R238.1 R251.2 R384.2 R401.2 R408.1 R478.2 R480.2 R483.1 R484.1 R485.1 R489.1 R494.2 R495.2 R500.2 R501.2 R502.2 R503.2 R504.2 R505.2 R506.2 R507.2 R508.2 R509.2 R510.2 R511.2 R512.2 R513.2 R514.2 R515.2 R532.2 R533.2 R534.2 R594.1 R599.2 R600.2 R603.1 R608.2 R609.2 R647.2 R648.2 U15.15 U15.16 U15.17 U16.5 U17.8 U18.8 U19.24 U20.14 U21.14 U22.8 U23.8 U24.14 U25.14 U30.1 U32.14 U33.14 U34.14 U35.14
V_STBY_3V3_VCXO1: C13.2 C94.2 C177.2 C179.2 LB15.2 OSC1.4 R4.1 VCXO1.4
V_STBY_5V0: C35.1 C123.2 C124.2 C125.2 C126.2 C254.1 C255.1 C256.1 C369.1 C370.1 J11.2 J11.4 L5.2 LB19.1 R274.1 R277.1 R391.2 R409.1 RT1.2(TP-2) RT2.2(TP-2) U8.6 U9.6
V_STBY_5V0_HDMI0: D17.1 RT1.1
V_STBY_5V0_HDMI1: D25.1 RT2.1
V_STBY_12V0: C32.2 C222.2 C223.2 C224.2 C225.2 C228.2 C229.2 C230.2 C231.2 C232.2 C235.1 C236.1 C241.1 C249.1 C257.1 C258.1 C259.1 C261.1 C306.1 C322.2 D41.1 J16.272 J16.273 J16.274 J16.275 J16.276 J16.277 J16.278 J16.279 J16.280 J16.281 Q11.1 Q11.2 Q11.3 R11.1 R370.2 R388.2 R394.2 U13.4 U13.5 U13.6 U14.1 U26.11
V_VCC_1V8_EMMC: C89.2 C98.2 C99.2 C100.2 Q2.3 R202.1 R203.1 R204.1 R205.1 R206.1 R207.1 R208.1 R209.1 R210.1 R211.1 U27.C6 U27.M4 U27.N4 U27.P3 U27.P5
V_VCC_3V3_BUF: C152.1 C155.1 C161.1 C163.1 LB13.2 R316.1 R322.1 R342.1 R344.1 U10.15 U10.42
V_VCC_3V3_EMMC: C91.2 C101.2 C102.2 C103.2 J3.4 Q3.3 U3.5 U4.5 U27.E6 U27.F5 U27.J10 U27.K9
V_VCCO_3V3_BUF: C156.1 C157.1 C158.1 C167.1 LB14.2 U10.5 U10.8 U10.29 U10.32 U10.45
V_VDD_3V3_PHY0: C48.2 C60.2 C61.2 C62.2 LB2.1 LB3.2 LB16.2 R97.1 R98.1 R99.1 R124.1 R126.1 U1.30 U1.31
V_VDD_3V3_PHY0_LED: C92.1 J17.20 LB16.1
V_VDD_3V3_PHY1: C74.2 C79.2 C80.2 C81.2 LB5.1 LB6.2 LB17.2 R153.1 R154.1 R155.1 R192.1 R194.1 U2.30 U2.31
V_VDD_3V3_PHY1_LED: C93.1 J17.22 J17.24 LB17.1
V_VDDI_EMMC: C88.1 U27.B1 U27.C2
XTAL_IN_PHY0: C46.1 R105.1 U1.45 X1.1
XTAL_IN_PHY1: C64.1 R172.1 U2.45 X2.1
XTAL_OUT_PHY0: R106.1 U1.46
XTAL_OUT_PHY1: R142.1 U2.46
$7N42483: L1.2 U1.32
$7N42484: R91.2 U1.48
$7N42485: R128.2 U1.15
$7N42486: R102.1 U1.38
$7N42487: R89.1 U1.39
$7N42488: R104.1 U1.40
$7N42489: R103.1 U1.41
$7N42494: C45.2 R129.2 U1.14
$7N42503: R101.2 U1.34
$7N42505: R90.1 R92.1 R93.1 R94.1 R95.1 R96.1 R115.2 R116.2 R118.1 R119.1
$7N42508: C47.2 R105.2 R106.2 X1.3
$7N63401: R137.1 U1.3
$7N63402: R130.1 U1.6
$7N63403: R131.1 U1.5
$7N63404: R132.1 U1.8
$7N63405: R133.1 U1.7
$7N63406: R134.1 U1.11
$7N63407: R135.1 U1.10
$7N63408: R136.1 U1.2
$8N37109: L2.2 U2.32
$8N37110: R169.2 U2.48
$8N37111: R182.2 U2.15
$8N37112: R165.1 U2.38
$8N37113: R164.1 U2.39
$8N37114: R167.1 U2.40
$8N37115: R166.1 U2.41
$8N37120: C68.2 R183.2 U2.14
$8N37128: R168.2 U2.34
$8N37132: C65.2 R142.2 R172.2 X2.3
$8N37208: R147.1 R148.1 R149.1 R150.1 R151.1 R152.1 R156.2 R157.2 R174.1 R175.1
$8N49706: R191.1 U2.3
$8N49707: R184.1 U2.6
$8N49708: R185.1 U2.5
$8N49709: R186.1 U2.8
$8N49710: R187.1 U2.7
$8N49711: R188.1 U2.11
$8N49712: R189.1 U2.10
$8N49713: R190.1 U2.2
$9N34271: C83.1 Q2.1 R196.1 R197.1 R214.1
$9N34273: C91.1 R198.2
$9N34274: C85.1 Q5.1 R1.2 R2.2 R201.2
$9N34275: Q5.3 R215.2
$9N34276: C84.1 Q3.1 R198.1 R199.1 R215.1
$9N34313: C89.1 R196.2
$9N34316: C90.1 Q4.1 R212.2 R213.2
$9N34317: Q4.3 R214.2
$12N40858: C118.1 R245.2 R306.2 R307.2
$12N40901: D5.1 R244.1 R245.1
$12N40902: R247.1 R248.2 U7.3
$12N40903: R249.1 U7.1
$12N40904: Q8.1 R249.2 R250.2
$12N40909: Q8.3 R251.1 R259.1
$12N55490: C308.1 U5.3
$12N55491: C310.1 U5.4
$12N56522: D7.2 LB8.1
$12N60383: R242.2 U5.2
$12N71093: R14.1 R18.2 U7.5
$12N71230: U7.6 U7.7
$13N103139: LB9.1 U8.1
$13N103140: R272.1 R273.2
$13N103141: R273.1 U8.2
$13N103146: LB10.1 U9.1
$13N103147: R275.1 R276.2
$13N103148: R276.1 U9.2
$16N50509: D27.2 LB12.1 MIC1.2
$16N50739: C147.1 MIC1.1 R314.1
$17N15518: R321.2 U10.16 U10.17
$17N15519: R319.2 U10.38
$17N15520: R315.2 U10.44
$17N15521: R320.2 U10.46
$17N51906: R114.2 U10.41
$17N51968: R170.2 U10.40
$17N56555: OSC1.1 R4.2 VCXO1.1
$17N57348: OSC1.3 R3.1 VCXO1.3
$17N59162: C15.2 R340.2 R341.2 R342.2 U10.21
$18N13054: C182.1 C183.1 D30.1 D32.2 J8.1 L3.2
$18N13056: D31.1 J8.3 R355.2
$18N13057: D31.2 R346.2 R347.1 R355.1
$18N13061: D29.2 R350.1
$18N13062: C309.2 D29.1 R351.1
$18N13063: Q10.1 R351.2
$19N38557: C185.2 C186.2 C187.2 C188.2 C189.1 C190.1 C191.1 T19.1 T19.4 T19.7 T19.10
$19N42379: C193.2 C194.2 C195.2 C196.2 C197.1 C198.1 C199.1 T20.1 T20.4 T20.7 T20.10
$19N46347: C201.1 J17.19 R365.1
$19N48969: C204.1 J17.21 R368.1
$19N48970: C203.1 J17.23 R367.1
$19N66318: R362.1 T19.15 T19.18 T19.21 T19.24
$19N66421: R363.1 T20.15 T20.18 T20.21 T20.24
$19N66917: C192.1 R362.2
$19N67094: C200.1 R363.2
$19N73517: C202.1 J17.18 R366.1
$20N78412: R369.1 R374.1 U12.10
$20N78416: R378.1 R379.2
$20N78417: C216.1 C218.2
$20N78418: D35.2 F1.2
$20N78419: C217.1 R372.1 R373.1
$20N78420: C212.1 C219.1 U12.4
$20N78421: C221.1 R378.2 U12.3
$20N78422: C213.2 R375.1
$20N78423: C215.1 R370.1 R376.2 U12.6
$20N78424: C214.2 R371.1 R377.2 U12.2
$20N78430: C226.2 R380.1 U12.8
$20N81774: Q11.4 R381.2
$20N97792: C211.2 R383.1
$20N102271: R357.1 U26.4
$20N102272: R356.1 R357.2
$20N102276: C321.2 U26.2
$20N112363: R11.2 R358.2 U26.3
$20N115775: R457.2 U11.1
$20N115843: D1.1 R457.1
$20N117364: R650.2 U26.1
$21N31413: C239.1 R385.1 R404.2 U13.7
$21N31414: C243.1 R387.2 R388.1 U13.10
$21N31415: C240.2 L4.1 R389.2 U13.11 U13.12
$21N31416: C242.1 U13.9
$21N31417: C240.1 U13.13
$21N31418: R390.2 U13.1
$21N31419: C234.1 R386.1 U13.8
$21N31420: C237.1 R389.1
$21N31421: C233.1 C244.1 R386.2
$21N31422: C239.2 R384.1 R385.2
$21N31423: R403.1 R404.1
$21N31428: R395.1 R407.2
$21N31429: R406.1 R407.1
$21N31430: R52.2 R392.1
$21N31431: C250.2 R391.1 R392.2
$21N31432: C251.2 L5.1 U14.2
$21N31433: C260.1 R393.2 R394.1 U14.5
$21N49359: C269.1 R399.1 R402.1 U15.3
$21N49360: C271.1 U15.13
$21N49363: C262.1 R10.2 R401.1 U15.14
$21N49365: C269.2 R396.1 R399.2
$21N59472: C251.1 U14.4
$21N69175: C250.1 R52.1 R406.2 U14.6
$45N4597: C273.1 LED1.4 R410.2
$45N4598: C274.1 LED1.3 R411.2
$45N4601: C276.1 Q12.1 R414.2
$45N4602: C277.1 Q13.1 R415.2
$45N5400: D3.2 R417.2
$45N7206: C280.1 LED3.4 R418.2
$45N7207: C281.1 LED3.3 R419.2
$45N7210: C283.1 Q14.1 R422.2
$45N7211: C284.1 Q15.1 R423.2
$45N10753: LED4.4 R54.2
$45N10784: LED4.3 R290.2
$46N66735: C21.2 J1.11
$46N66736: C22.2 J1.13
$46N66739: C25.2 J1.23
$46N66740: C26.2 J1.25
$46N92195: J1.69 R16.2
$46N95153: J1.38 R22.1
$46N95508: J1.50 R23.1
$46N114099: C2.2 J1.37
$46N114100: C3.2 J1.35
$47N4437: J2.55 R43.2
$47N4444: J2.34 R46.1
$47N4445: J2.22 R47.1
$47N4481: J2.53 R70.2
$47N8328: J2.8 R55.1
$47N8362: J2.10 R45.1
$47N11242: J2.58 R59.1
$47N11243: J2.60 R58.1
$47N12203: J2.12 R62.1
$47N12239: J2.14 R63.1
$47N17143: J2.32 R68.1
$47N18593: J2.36 R69.1
$47N36111: J2.20 R44.1
$47N40951: C42.2 J2.37
$47N40952: C41.2 J2.35
$47N43343: J2.3 R416.2
$47N43374: J2.5 R424.2
$49N8755: J10.43 R427.1
$49N8793: J10.42 R428.2
$49N16307: J11.3 R444.1
$49N16308: J11.5 R445.1
$49N16309: J11.10 R433.2
$49N16311: J11.19 R439.2
$49N16312: J11.21 R438.2
$49N16313: J11.23 R437.2
$49N16315: J11.16 R435.2
$49N16316: J11.18 R440.2
$49N16317: J11.24 R436.2
$49N16328: J11.37 R452.1
$49N16335: J11.27 R449.1
$49N16337: J11.28 R442.2
$49N16343: J11.32 R443.2
$49N16344: J11.35 R453.1
$49N16346: J11.38 R455.2
$49N16347: J11.12 R454.2
$49N16348: J11.40 R456.2
$49N16355: J11.15 R448.1
$49N18559: R594.2 U22.5
$49N18560: R595.2 U22.2
$49N18561: R596.2 U22.3
$49N18572: R603.2 U23.5
$49N18573: R604.2 U23.2
$49N18574: R605.2 U23.3
$49N23298: R253.2 U30.6
$49N23299: R252.2 U30.7
$49N23309: R254.2 U30.4
$49N25648: J11.7 R288.1
$49N25997: J11.29 R450.1
$49N29598: J11.11 R447.1
$49N29990: J11.36 R258.2
$49N30030: J11.22 R289.2
$49N33582: J11.8 R51.2
$49N34084: J11.31 R21.1
$49N34222: J11.26 R29.2
$49N34367: J11.33 R56.1
$49N34520: J11.13 R57.1
$49N38048: J10.47 R426.1
$49N38251: J10.46 R425.2
$50N4470: R470.1 SW1.6
$50N4927: C289.1 U16.4
$50N4929: Q16.3 R478.1 U16.3
$50N5621: Q16.1 R479.1
$50N7178: R469.1 SW1.5
$50N10237: R471.1 SW1.7
$50N10250: R472.1 SW1.8
$51N171791: R237.2 U20.3
$51N171792: R635.2 U20.2
$51N172159: R575.2 U20.4
$51N172500: R637.2 U20.5
$51N175745: R638.2 U32.5
$51N176453: R669.2 U32.4
$51N176454: R674.2 U32.3
$51N176455: R636.2 U32.2
$51N179684: R589.1 U20.8
$51N179736: R591.1 U32.8
$51N184426: R622.2 U24.3
$51N184427: R623.2 U24.2
$51N184759: R291.2 U24.4
$51N185068: R626.2 U24.5
$51N185452: R614.1 U24.12
$51N185453: R615.1 U24.13
$51N185799: R618.1 U24.10
$51N186799: R628.1 U24.8
$51N188619: R617.1 U25.12
$51N188623: R613.1 U25.10
$51N188624: R616.1 U25.11
$51N189028: R621.2 U25.5
$51N189029: R624.2 U25.4
$51N189030: R625.2 U25.3
$51N189031: R627.2 U25.2
$51N193077: R678.2 U21.2
$51N193392: R676.2 U21.3
$51N193887: R553.1 U21.8
$51N194066: R629.1 U33.8
$51N194833: R5.2 U21.4
$51N194878: R6.2 U21.5
$51N196011: R612.2 U33.3
$51N196013: R671.2 U33.2
$51N196656: R19.2 U33.5
$51N196657: R7.2 U33.4
$51N198291: R634.2 U34.2
$51N198558: R620.2 U34.3
$51N199282: R670.2 U34.4
$51N199818: R641.2 U34.5
$51N202756: R239.1 U34.8
$51N202938: R552.1 U35.8
$51N203980: R53.2 U35.2
$51N204476: R557.2 U35.3
$51N204970: R572.2 U35.4
$51N205764: R556.2 U35.5
$51N207141: R20.1 U25.8
$52N827: R482.1 U17.6
$52N828: R481.1 U17.5
$52N832: R485.2 R487.1 U17.1
$52N833: R483.2 R486.1 U17.2
$52N834: R484.2 R488.1 U17.3
$52N843: R489.2 U18.5
$52N844: R492.1 U18.6
$52N845: R493.1 U18.7
$52N846: R490.2 U18.2
$52N847: R491.2 U18.3
$52N2706: R498.1 U19.23
$52N2707: R499.1 U19.22
$55N3286: R459.2 U36.1
$55N3381: C307.1 Q1.3 R549.1
$55N3383: R550.2 U36.40
$55N3386: C317.1 R558.2 R560.1 X3.1
$55N3387: C314.1 R559.2 R560.2 X3.3
$55N29278: C312.1 Q6.3 R555.1
$55N30280: R458.2 U36.41
$55N32703: R649.2 U36.16 U36.28
$56N3501: R562.2 U37.2
$56N3504: R607.2 U37.3
$56N3505: R561.1 U37.6
$56N3511: R563.1 U37.1
$56N3513: R567.2 U37.5
$56N3514: R619.2 U37.7
$56N3541: R570.1 U38.57
$56N3566: R573.2 U38.23
$56N3571: R570.2 R574.1
$56N3579: C343.1 R578.1 R580.2 X4.1
$56N3581: C344.1 R578.2 R579.2 X4.3
$56N19655: R651.2 U38.27
$56N19722: R652.1 U38.41

Pads without a net: D1 2; D17 2; D18 2; D25 2; D27 3 4 5 6; ID1 1; ID2 1; ID3 1; J1 6 8 10 20 22 24 26 28 30 32 34 36 40 42 44 46 48 56 58 59 60 61 62 63 64 65 66 67 68; J2 6 16 24 25 26 27 28 29 30 31 38 40 42 44 46 48 50 54 56 59 61 62 65 66 67 68 70 71 73; J4 8 20; J6 14; J7 14; J10 1 2 3 4 5 6 7 9 10 12 13 15 16 18 19 21 37 39 40 48 49 52 53; J16 8 10 33 35 62 63 64 65 68 69 70 71 74 75 76 77 80 81 82 83 110 111 112 113 114 120 122 124 126 127 128 129 130 131 132 179 287 293 307 309; NOREF#31 A1 A2 A3 B1 B2 B3 C1 C2 C3; NOREF#32 A1 A2 A3 B1 B2 B3 C1 C2 C3; NOREF#34 A1 A2 A3 B1 B2 B3 C1 C2 C3; NOREF#35 A1 A2 A3 B1 B2 B3 C1 C2 C3; TP8 2; TP9 2; U1 33 42 43 44; U2 33 42 43 44; U4 4; U10 3 4 9 10 23 25 26 27 28 30 31 33 34 35 36 39; U12 1; U13 14; U15 2 4 5 6 7 9 10 11 12; U17 7; U19 1; U20 6 9; U21 6 9; U24 6 9; U25 6 9; U26 5; U27 A7 A9 A10 A11 A12 A13 A14 B8 B9 B10 B11 B12 B13 B14 C1 C7 C8 C9 C10 C11 C12 C13 C14 D1 D4 D12 D13 D14 E1 E2 E5 E8 E9 E10 E12 E13 E14 F1 F2 F10 F12 F13 F14 G1 G2 G3 G10 G12 G13 G14 H1 H2 H3 H12 H13 H14 J1 J2 J3 J12 J13 J14 K1 K2 K3 K6 K7 K10 K12 K13 K14 L1 L2 L3 L12 L13 L14 M1 M2 M3 M7 M8 M9 M10 M11 M12 M13 M14 N3 N6 N7 N8 N9 N10 N11 N12 N13 N14 P1 P2 P7 P8 P9 P10 P11 P12 P13 P14; U31 5; U32 6 9; U33 6 9; U34 6 9; U35 6 9; U36 14 15 17 18 20 21 23 24 26 27 29 30 32 33 36 37 38 39 42 43; U38 10 11 13 14 16 17 28 30 31 42 59 60 62 63 65 66

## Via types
v1: diameter 0.457, hole 0.203, TOP to BOTTOM, 2475 vias

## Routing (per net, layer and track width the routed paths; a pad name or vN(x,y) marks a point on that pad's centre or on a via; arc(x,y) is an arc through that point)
3V3_USB30_SW: length 9.4
  TOP w0.254: U5.10 105.49,14.4 105.34,14.55 R241.1 104.93,14.71 105.38,15.16 v1(105.54,15.16) ; U5.6 107.93,15.94 v1(108.1,16.11) C113.2 ; v1(111.45,15.32) C115.2 111.02,14.55 110.87,14.4 U5.1
  TOP w0.381: v1(105.54,15.16) 105.54,15.44 105.18,15.8 105.18,15.88 104.29,16.76 D7.1
12V_FAN: length 7
  TOP w0.254: v1(120.83,107.34) 121.39,107.34 R353.2
  ART03 w0.254: v1(115.52,108.7) 115.52,107.87 116.05,107.34 v1(120.83,107.34)
AGND_AUDIO: length 130.4
  TOP w0.254: J16.302 102.25,47.36 ; J16.305 102,53.49
  ART03 w0.254: v1(102.74,46.86) 102.74,47 103.37,47.62 103.9,47.62 104.87,48.59 111.33,48.59 111.91,49.17 128.91,49.17 132.82,45.27 132.82,42.68 133.78,41.72 133.78,37.47 134.12,37.13 v1(134.24,37.13) ; v1(102.74,46.86) 102.08,47.52 100.69,47.52 100.3,47.14 100.3,46.13 102.06,44.37 105.26,44.37 106.22,45.34 112.67,45.34 113.26,45.92 127.56,45.92 129.53,43.95 129.53,40.53 ; v1(102.74,46.86) 103.25,46.35 104.44,46.35 105.4,47.32 111.85,47.32 112.44,47.9 128.38,47.9 131.55,44.74 131.55,42.16 132.51,41.19 132.51,40.23 ; v1(134.24,35.33) 134.06,35.33 132.51,36.88 132.51,40.23 ; 129.53,40.53 130.54,39.52 131.64,39.52 132.35,40.23 132.51,40.23 ; 129.53,40.53 129.05,41.01 v1(128.96,41.01)
AGND_MIC: length 4.4
  TOP w0.254: 130.82,36.87 D27.1 130.82,38.92 130.09,39.65 R257.1 LB11.1
DVDD_PHY0_RG: length 39.8
  TOP w0.203: C63.2 33.3,40.61 33.4,40.51 v1(33.66,40.51) 34.37,40.51 R115.1 ; U1.29 12.35,57.75 12.24,57.86 12.24,58.06 v1(11.94,58.37)
  ART03 w0.203: v1(11.94,58.37) 11.94,56.39 11.17,55.62 11.17,48.9 11.26,48.68 11.91,48.04 11.91,46.86 12.12,46.65 12.12,46.62 12.38,46.36 12.41,46.36 13.71,45.06 14.25,44.83 15.49,44.83 16.37,43.95 19.65,42.6 30.26,42.6 32.39,41.17 32.73,41.17 33.4,40.51 v1(33.66,40.51)
DVDD_PHY1_RG: length 4.8
  TOP w0.203: U2.29 58.51,38.12 58.66,38.26 58.66,38.26 59.09,38.7 59.09,40.21 59.32,40.44 R157.1
  TOP w0.254: R157.1 C82.2
GND: length 695.3
  TOP w0.127: U27.N1 U27.N2 ; v1(8.02,94.62) 8.02,94.45 U27.D3 U27.C4 ; U27.N5 U27.P6
  TOP w0.203: C298.2 v1(117.99,56.69) ; R200.1 v1(68.89,75.87) ; v1(59.44,17.53) 60.02,16.94 U28.2 ; C180.2 94.15,85.55 U36.51 94.15,81.42 v1(95.35,80.22) ; R287.1 v1(60.5,21.62) ; R235.1 v1(96.57,59.59) ; C17.1 v1(73.88,81.98) ; v1(107.59,89.26) 107.85,89 C312.2 ; C87.1 v1(20.89,92.89) ; R217.1 v1(68.89,71.62) ; C307.2 v1(74.27,94.82) ; R548.1 v1(75.72,90.45) ; R173.1 v1(72.06,73.05) ; U36.61 91.58,82.62 v1(91.67,82.52) ; C139.1 v1(73.88,76.19)
  TOP w0.254: C145.2 82.96,15.57 R305.1 82.45,14.58 v1(82.3,14.73) ; v1(111,54.56) 111.5,54.06 J16.322 ; X2.4 52.02,33.45 v1(52.02,32.89) ; J11.39 132.68,108.31 v1(132.09,107.72) ; v1(93,54.79) J16.19 v1(93,57.64) ; J11.6 127.35,66.41 v1(127.16,66.6) ; U37.4 26.17,118.65 v1(26.76,119.24) ; v1(22.99,107.95) C104.2 22.38,108.13 22,108.51 19.96,108.51 19.66,108.2 R223.2 ; v1(84,54.79) J16.55 v1(84,57.64) ; C301.1 v1(110.95,70.27) ; v1(56.9,111.89) 56.9,112.22 57.32,112.65 U10.48 ; v1(96.85,97.97) C326.1 C325.1 C339.2 ; R526.1 v1(109.9,99.19) ; R248.1 R246.1 C120.1 97.79,20.78 v1(97.79,20.19) ; v1(81.25,47.29) J16.66 v1(81.25,50.13) ; C321.1 R650.1 ; C321.1 R358.1 ; C321.1 110.72,114.07 v1(110.72,114.07) ; v1(18.26,83.38) 17.93,83.71 J2.18 ; J16.190 v1(50.25,50.13) ; v1(91.5,57.64) J16.25 v1(91.5,54.79) ; v1(116.43,61.1) 116.42,61.09 U32.7 ; R352.1 120.9,104.32 120.57,104.65 Q10.2 v1(120.04,105.71) ; J16.195 v1(49,54.71) ; v1(42.57,21.52) 42.65,21.6 D9.3 D9.8 42.65,25.47 v1(42.65,25.48) ; S1.5 131.33,28.52 S1.4 ; S1.5 v1(129.92,29.64) ; S1.5 128.52,28.52 S1.3 ; v1(123.27,41.2) 123.07,41.39 J1.9 v1(118.81,41.39) ; v1(118.11,98.96) 118.39,99.24 U19.12 ; v1(84.25,50.13) J16.54 v1(84.25,47.29) ; v1(62.48,115.4) 62.73,115.15 U10.18 ; v1(89,40.17) 89.12,40.28 R420.2 C284.2 ; R27.2 C34.2 v1(111.71,33.99) ; U29.2 v1(80.54,15.85) ; v1(66.92,12) 66.87,11.95 J6.5 v1(66.87,8.67) ; v1(5.97,95.05) 6.07,95.05 6.56,94.56 U27.E7 ; R405.1 54.56,67.26 v1(54.61,67.31) ; U25.7 82.15,86.33 82.14,86.34 v1(81.76,86.34) ; v1(42.25,47.31) J16.222 v1(42.25,50.13) ; R527.1 v1(109.9,98.17) ; v1(127.84,42.16) 127.66,42.34 R472.2 ; v1(127.84,42.16) C43.1 C39.1 ; v1(127.84,42.16) 128.07,42.39 129.57,42.39 ; R487.2 v1(120.29,101.35) ; v1(52.58,102.62) 52.64,102.56 C90.2 R213.1 ; v1(37.96,21.48) 37.93,21.5 D10.3 D10.8 37.93,24.57 v1(37.9,24.6) ; 129.57,42.39 129.64,42.47 131.17,42.47 131.34,42.65 R470.2 ; 129.57,42.39 R471.2 ; Q5.2 v1(40.26,112.95) ; R518.1 v1(122.99,98.27) ; v1(10.03,62.37) 9.65,61.99 C62.1 ; v1(85.5,57.64) J16.49 v1(85.5,54.79) ; R144.2 52.09,42.85 51.59,42.34 v1(51.59,42.09) 51.59,41.25 R145.2 ; C69.1 49.02,27.89 R272.2 C127.2 R278.1 45.77,27.2 v1(45.85,27.13) ; R531.1 v1(109.9,94.11) ; R528.1 v1(109.9,97.16) ; v1(39.25,47.31) J16.234 v1(39.25,50.13) ; J3.10 17.67,91.56 v1(18.47,90.76) ; v1(122.5,33.9) J1.39 v1(120.27,33.9) ; v1(102.46,7.72) 103.1,7.08 J4.1 ; R517.1 v1(122.99,99.29) ; C208.2 C279.2 R459.1 89.23,72.82 v1(89.23,72.14) ; R166.2 v1(50.62,36.45) ; J2.33 v1(14.17,77.05) ; R164.2 v1(50.62,37.72) ; v1(82.88,18.39) C233.2 C244.2 R387.1 ; R102.2 8.93,70.24 R103.2 v1(9.79,70.24) ; R408.2 v1(94.92,27.2) ; v1(22.96,74.6) C264.2 R127.2 R138.2 ; v1(8.26,99.69) 8.06,99.5 U27.P4 ; J11.20 129.19,83.31 v1(129.55,83.67) ; R336.2 v1(72.62,110.92) ; R387.1 C243.2 ; R387.1 84.75,18.39 84.48,18.11 v1(84.06,18.11) ; U22.4 93.35,114.54 v1(93.25,114.44) ; v1(73.5,54.79) J16.97 v1(73.5,57.64) ; v1(96,54.79) J16.7 v1(96,57.64) ; v1(46.75,50.13) J16.204 v1(46.75,47.31) ; R138.2 v1(22.28,71.63) ; R138.2 C45.1 22.64,70.16 22.64,68.96 22.9,68.71 R117.2 ; C36.1 v1(128.91,33.25) ; D23.8 D23.3 87.58,12.57 v1(87.68,12.47) ; v1(87.72,119.24) 87.35,118.87 C292.1 ; v1(72.25,50.13) J16.102 v1(72.25,47.29) ; v1(107.85,83.46) C313.1 R554.1 ; C299.2 v1(111.44,59.56) ; C37.1 v1(26.29,84.96) ; v1(65.62,12.02) 65.37,11.77 J6.8 v1(65.37,8.67) ; U34.7 116.3,84.81 v1(116.33,84.84) ; v1(103.72,42.24) 104.93,42.24 R369.2 ; v1(91.56,12) 91.48,11.92 J7.2 v1(91.48,8.67) ; R535.1 v1(122.99,92.18) ; v1(92.68,41.69) 92.94,41.44 93.06,41.44 94.21,40.28 C281.2 ; C288.2 97.38,43.23 98.17,44.02 C289.2 100.76,44.53 v1(100.91,44.37) U16.2 ; v1(88.75,47.29) J16.36 v1(88.75,50.13) ; v1(86.98,8.67) J7.11 86.98,11.95 v1(86.93,12) ; v1(90.73,12.47) 90.63,12.57 D21.3 D21.8 ; v1(70.03,14.02) 69.95,14.02 D13.8 D13.3 ; R376.1 106.74,36.36 107.01,36.09 v1(107.01,36.07) 107.18,36.23 C215.2 ; v1(72,57.64) J16.103 v1(72,54.79) ; J11.9 131.18,70.61 v1(130.19,71.6) ; R143.2 v1(65.61,40.72) R179.2 ; v1(75,54.79) J16.91 v1(75,57.64) ; U14.3 73.22,18.25 ; v1(81.68,80.42) 82.06,80.42 82.07,80.41 U24.7 ; v1(46.94,27.08) 46.96,27.05 U31.2 ; R177.2 v1(61.89,40.72) R181.2 61.25,40.7 C44.2 ; v1(87.25,47.29) J16.42 v1(87.25,50.13) ; C51.1 v1(15.22,48.97) ; U17.4 116.98,103.11 v1(116.23,102.36) ; v1(96.01,20.19) 95.96,20.24 C119.2 ; R120.2 v1(44.15,43.28) ; R257.2 129.73,38.21 v1(129.74,38.2) ; R348.1 111.99,105.46 111.48,104.95 R350.2 v1(111.48,103.99) ; R122.2 v1(47.96,43.28) ; C296.2 v1(117.51,68.23) ; v1(60.87,8.67) J6.17 60.87,12.13 v1(60.65,12.35) ; R35.1 100.74,57.87 v1(100.5,57.64) J16.311 ; v1(18.41,104.14) 18.67,103.89 U4.2 ; U27.J5 7.38,96.41 v1(6.88,95.91) 7.38,95.41 U27.G5 ; R139.2 25.27,58.57 v1(25.27,58.29) ; v1(68.37,8.67) J6.2 v1(68.37,11.97) ; J16.183 v1(52,54.71) ; v1(122.33,61.1) 122.33,61.09 U20.7 ; C303.1 111.4,77.55 v1(111.36,77.51) ; v1(11,62.36) 10.62,61.98 C61.1 ; S3.4 131.33,17.34 S3.5 ; v1(63.87,8.67) J6.11 63.87,11.92 v1(63.82,11.97) ; R167.2 R165.2 R146.2 v1(48.21,38.48) ; v1(122.22,84.43) 122.01,84.22 U35.7 ; C295.2 83.09,75.08 82.88,74.87 v1(82.4,74.87) ; v1(60.2,24.13) 60.99,24.92 C141.2 ; v1(9.77,99.45) 10,99.21 10,98.68 9.74,98.41 U27.N1 ; J10.41 v1(1.93,70.65) ; R523.1 v1(122.99,93.19) ; S2.5 v1(129.92,24.05) ; S2.5 128.52,22.93 S2.3 ; S2.5 131.33,22.93 S2.4 ; C73.1 59.74,28.62 59.87,28.49 v1(59.87,28.22) ; J16.176 v1(53.75,49.97) ; v1(62.48,114.13) 63.96,112.65 U10.13 ; J16.308 v1(100.75,50.13) ; v1(37.75,47.31) J16.240 v1(37.75,50.13) ; v1(105.49,10.69) 105.03,10.24 U6.2 ; v1(88.65,106.3) 89.03,105.92 C367.2 R633.1 ; v1(120.27,35.39) J1.33 123.48,35.39 v1(123.95,34.92) ; v1(120.27,30.9) J1.51 v1(122.5,30.9) ; v1(116.31,72.76) 116.3,72.76 U33.7 ; v1(111.45,12.97) C115.1 111.02,13.74 110.86,13.9 U5.20 ; v1(64.04,37.44) 64.04,37.09 63.61,36.66 C70.1 ; v1(118.81,39.9) J1.15 v1(122.5,39.9) ; v1(27.36,92.03) 26.76,91.44 C86.1 ; U5.11 105.49,13.9 105.33,13.74 R241.2 104.93,13.12 v1(105.36,12.7) ; R250.1 v1(96.27,35.97) ; R318.2 52.88,114.94 v1(52.32,114.94) ; v1(58.06,23.81) 58.27,24.01 D2.3 ; v1(43.75,50.13) J16.216 v1(43.75,47.31) ; C219.2 v1(96.34,38.1) ; C56.1 v1(10.53,47.78) ; J2.51 v1(9.68,79.48) ; v1(21.05,112.77) 21.04,112.78 C318.2 ; v1(34.75,47.31) J16.252 34.75,49.9 v1(34.63,50.03) ; v1(36.25,47.31) J16.246 v1(36.25,50.13) ; J10.11 v1(1.93,61.65) ; J16.140 62.75,50.03 v1(62.61,50.16) ; v1(76.5,57.64) J16.85 v1(76.5,54.79) ; v1(122.5,29.39) J1.57 v1(120.27,29.39) ; v1(21.18,64.14) 21.23,64.14 21.62,64.52 R140.2 ; v1(40.75,50.13) J16.228 v1(40.75,47.31) ; R26.2 v1(111.83,30.6) ; v1(33.25,50.13) J16.258 v1(33.25,47.31) ; v1(94.5,54.79) J16.13 v1(94.5,57.64) ; C136.1 v1(91.49,110.41) ; J10.44 v1(4.81,71.55) ; Q6.2 107.85,87.8 C312.2 ; v1(6.99,91.57) 7.06,91.64 U27.A6 ; C82.1 58.93,42.06 v1(58.7,42.29) ; v1(75.25,50.13) J16.90 v1(75.25,47.29) ; C234.2 C242.2 v1(85.42,20.85) ; J16.151 v1(60,54.79) ; J4.12 108.6,6.96 108.85,7.21 109.18,7.21 v1(109.41,7.44) ; v1(82.83,93.45) 82.61,93.23 R574.2 ; J10.14 v1(4.81,62.55) ; v1(134.24,30.62) 134.24,31.88 133.68,32.44 C285.1 ; v1(97.88,119.24) 97.21,118.57 C291.2 ; v1(95.99,100.99) 95.99,100.61 95.5,100.12 C327.1 ; v1(79.75,47.29) J16.72 v1(79.75,50.13) ; R521.1 v1(122.99,95.22) ; v1(39.74,59.05) 39.17,59.05 37.5,57.39 J16.241 ; v1(83.79,39.53) 83.34,39.99 C283.2 R421.1 ; C207.2 v1(87,74.32) ; J2.63 v1(6.68,79.48) ; v1(81.07,18.29) 81.81,19.02 R403.2 ; v1(20.19,76.96) 20.33,76.96 20.68,77.31 J2.7 ; v1(78.25,47.29) J16.78 v1(78.25,50.13) ; Q4.2 v1(49.78,99.57) ; v1(111.83,27.16) C18.1 R28.2 ; v1(81,57.64) J16.67 v1(81,54.79) ; C116.1 97.96,4.99 v1(97.97,4.98) ; C273.2 72.95,40.41 72.34,41.02 Q12.2 70.99,39.88 v1(70.99,38.99) C276.2 ; v1(96.55,40.82) 96.55,40.49 97.03,40.01 R379.1 97.66,39.99 C221.2 ; J2.57 v1(8.17,79.48) ; v1(107.44,57.66) 107.25,57.66 107,57.4 J16.285 ; R516.1 v1(122.99,100.3) ; v1(82.5,57.64) J16.61 v1(82.5,54.79) ; v1(127.01,97) 127.35,96.66 J11.30 ; J16.271 30,54.63 30.15,54.48 30.48,54.48 ; U5.5 108.43,14.4 v1(108.18,14.15) ; C133.2 86.49,111.53 ; C129.1 v1(108.97,87.25) ; C132.2 v1(117.66,79.9) ; R338.2 50.06,114.17 v1(50.01,114.22) ; R275.2 C134.2 R279.1 56.34,13.34 v1(56.21,13.46) ; v1(91.28,116.13) 91.11,116.31 U18.4 ; v1(125.98,37.36) 125.85,37.23 U30.5 ; J11.25 132.09,91.52 v1(132.09,91.92) ; C76.1 C77.1 53.19,27.98 v1(53.37,27.81) ; J10.35 v1(1.93,68.85) ; R17.1 122.68,26.02 122.55,25.9 J1.71 ; v1(120.27,32.39) J1.45 v1(122.5,32.39) ; v1(66.5,38.5) R178.2 ; v1(78,57.64) J16.79 v1(78,54.79) ; U10.24 65.06,118.15 65.42,118.51 ; R400.1 54.23,63.25 v1(54.61,62.87) ; J2.75 v1(3.68,79.48) ; C50.1 6.55,50.17 6.55,50.17 C49.1 6.52,50.32 v1(5.91,50.32) ; C237.2 82.75,27.76 R390.1 ; C131.2 v1(111.96,79.9) ; v1(7.32,45.39) 7.32,46.66 C60.1 ; R631.2 v1(31.62,115.19) ; v1(110.17,10.9) D6.3 D6.8 ; v1(88.48,8.67) J7.8 v1(88.48,12) ; R524.1 v1(109.9,101.22) ; J3.6 15.69,98.61 v1(15.24,99.06) ; R488.2 v1(120.29,103.38) ; v1(90,54.79) J16.31 v1(90,57.64) ; C348.2 C342.1 v1(96.01,104.42) ; R309.2 25.15,103.25 v1(26.04,102.36) ; C109.2 v1(11.53,60.58) ; J16.270 30.25,49.9 v1(30.48,50.13) ; v1(60.32,109.47) 60.31,109.47 C157.2 ; v1(122.5,38.39) J1.21 v1(118.81,38.39) ; C38.1 126.92,33.25 126.38,32.71 v1(126.38,32.44) ; R522.1 v1(122.99,94.21) ; v1(70.69,111.91) 70.28,111.51 R334.2 ; v1(92.02,106.05) 91.92,105.94 C334.2 R573.1 ; v1(76.75,50.13) J16.84 ; R337.2 50,111.48 v1(49.97,111.45) ; C144.2 v1(78.82,12.75) ; J16.154 v1(59.25,50.13) ; R10.1 86.43,33.07 C271.2 ; R10.1 C262.2 ; R10.1 v1(85.67,33.73) ; R8.2 v1(96.14,44.02) ; R216.2 v1(41.38,84.3) ; v1(88.5,57.64) J16.37 v1(88.5,54.79) ; v1(97.5,54.79) J16.1 v1(97.5,57.64) ; R402.2 85.95,39.14 v1(85.7,38.9) ; J2.45 v1(11.17,77.05) ; C286.1 v1(132.3,21.95) ; v1(45.25,47.31) J16.210 v1(45.25,50.13) ; v1(85.75,50.13) J16.48 v1(85.75,47.29) ; J10.26 v1(4.81,66.15) ; J16.171 v1(55,54.71) ; R9.2 v1(97.16,44.02) ; C158.2 v1(55.48,114.12) ; J16.223 v1(42,54.57) ; U27.P6 v1(7.06,99.62) ; v1(106.98,10.95) D4.3 D4.8 ; R123.2 v1(46.69,43.28) ; C53.1 v1(12.78,47.78) ; C151.2 54.38,43.94 v1(54.41,43.97) ; v1(74.4,114.94) R329.2 73.89,115.7 R317.2 73.3,115.32 R330.2 ; v1(4.56,95.69) 4.78,95.91 U27.H10 ; R222.2 v1(43.4,79.48) ; C138.1 v1(101.73,117.98) ; C238.2 v1(94.92,21.95) ; v1(59.94,115.4) 59.69,115.15 U10.43 ; C203.2 C93.2 C204.2 C202.2 v1(31.27,20.44) ; U23.4 v1(106,115.48) ; v1(76.67,24.21) 76.51,24.05 R393.1 C260.2 ; C280.2 86.97,40.28 Q14.2 85.82,41.44 v1(85.7,41.44) ; C274.2 79.73,41.3 Q13.2 79.38,42.05 v1(78.71,42.71) ; v1(118.81,36.9) J1.27 v1(122.5,36.9) ; C75.1 63.57,30.71 v1(63.83,30.45) 63.83,30.2 63.55,29.92 C143.2 ; J10.8 v1(4.81,60.75) ; C137.2 111.85,118.62 v1(111.85,119.24) ; J10.32 v1(4.81,67.95) ; J16.253 34.5,54.31 35.03,53.78 35.03,51.86 v1(34.75,51.58) ; U12.5 101.72,38.78 v1(101.96,38.54) ; U7.4 v1(100.64,25.12) 101.19,25.12 101.45,24.87 101.45,24.21 101.7,23.95 R18.1 ; U3.2 v1(23.5,98.3) ; v1(70.75,50.13) J16.108 v1(70.75,47.29) ; v1(5.82,97.41) 6.06,97.16 U27.K8 ; C72.1 v1(55.54,28.64) ; C118.2 R307.1 98.83,9.81 98.83,11.58 99.45,12.2 D5.2 ; R395.2 v1(76.76,18.61) 76.66,18.51 C146.2 ; R525.1 v1(109.9,100.2) ; v1(83.98,12) J7.17 v1(83.98,8.67) ; R519.1 v1(122.99,97.26) ; U13.3 81.98,24.96 ; R530.1 v1(109.9,95.12) ; C140.1 v1(117.2,77.51) ; R486.2 v1(120.29,102.36) ; R201.1 C85.2 v1(40.61,116.28) ; R195.2 C265.2 C68.1 65.88,35.01 v1(66.5,35.01) 67.09,35.01 R176.2 ; R529.1 v1(109.9,96.14) ; v1(79.5,54.79) J16.73 v1(79.5,57.64) ; v1(130.18,16.33) 129.92,16.59 S3.5 ; v1(73.75,50.13) J16.96 v1(73.75,47.29) ; R100.2 v1(42.88,43.28) ; v1(129.6,101.09) 129.6,101.09 J11.34 ; C33.2 84.15,81.31 v1(84.15,80.8) ; U10.37 58.46,118.15 v1(59.94,116.67) ; C184.2 v1(124.38,109.11) ; J2.69 v1(5.17,79.48) ; R520.1 v1(122.99,96.24) ; v1(78.74,102.49) 78.77,102.51 C328.2 C336.2 C323.2 ; v1(94.72,30.78) 94.94,31.01 Q8.2 ; S3.5 128.52,17.34 S3.3 ; J2.39 v1(12.68,77.05) ; R170.1 R114.1 C152.2 55.04,115.95 v1(54.81,116.18) ; J16.12 v1(94.75,47.29) ; R141.2 45.42,43.27 v1(45.43,43.28) ; v1(121.58,72.87) 122,72.44 U21.7 ; C300.1 v1(117.4,65.84) ; v1(70.5,54.79) J16.109 v1(70.5,57.64) ; v1(82.75,47.29) J16.60 v1(82.75,50.13) ; C16.1 111.28,39.55 111.28,39.02 110.74,38.48 R25.2 109.93,38.25 R375.2 ; J10.29 v1(2.11,67.05) ; C214.1 R377.1 96.42,42.06 v1(96.09,41.73) ; C277.2 R412.2 74.53,41.3 v1(74.42,41.4) ; v1(89.98,8.67) J7.5 89.98,11.95 v1(89.93,12) ; C304.2 v1(111.95,68.23) ; v1(66.29,114.68) 65.91,114.3 C161.2 ; v1(70.69,114.15) 70.28,114.55 R333.2 ; D15.8 D15.3 65.02,12.62 v1(64.69,12.29) ; J10.38 v1(4.81,69.75) ; C287.1 v1(132.3,27.53) ; R537.1 v1(109.9,93.09) ; C142.2 R287.1 ; J10.20 v1(4.81,64.35) ; J16.298 103.25,50.29 103.09,50.45 103.09,50.85 103.63,51.39 v1(103.63,51.94) ; J10.17 v1(1.93,63.45) ; C88.2 9.15,105.39 9.85,104.7 v1(9.85,104.33) ; v1(68.58,42.7) R413.1 ; R321.1 v1(68.58,114.55) ; v1(129.55,76.05) 129.19,75.69 J11.14 ; J16.168 v1(55.75,50.13) ; R548.1 C311.1 75.81,92.3 Q1.2 ; C130.1 v1(117.15,89.17) ; R383.2 v1(114.68,24.08) ; v1(90.25,47.29) J16.30 v1(90.25,50.13) ; v1(87,54.79) J16.43 v1(87,57.64) ; J10.23 v1(2.11,65.25) ; C52.1 v1(5.81,51.44) ; C102.1 v1(33.4,114.1) ; C212.2 v1(96.34,36.85) ; R536.1 v1(122.99,91.16) ; 112.9,101.35 v1(112.29,101.35) ; 120.52,43.39 120.27,43.14 v1(120.27,42.9) J1.3 v1(122.5,42.9) 122.5,43.14 122.25,43.39 J1.1 120.52,43.39
  ART03 w0.254: v1(42.16,29.23) 42.62,28.77 42.62,28.5 ; v1(96.88,91.44) 96.72,91.44 95.38,90.09 95.38,87.38 92.18,84.18 91.03,84.18 v1(88.86,82)
  BOTTOM w0.254: v1(89.42,85.79) 89.42,85.31 89.52,85.21 89.52,85.09 89.85,84.76 89.85,83.76 90.32,83.29 90.32,78.68 v1(88.81,77.17) 88.81,76.95 87.83,75.97 v1(85.4,75.97) 85.01,75.97 84.21,76.3 80.16,76.3 77.65,73.79 77.65,69.05 v1(76.45,67.86) ; v1(87,74.32) 84.85,74.32 83.52,74.87 v1(82.4,74.87) 80.85,74.87 79.12,73.14 79.12,66.83 77.7,65.41 v1(76.45,65.41)
  vias: v1(0.76,101.22) v1(0.76,97.41) v1(0.76,96.14) v1(0.76,94.87) v1(0.76,93.6) v1(0.76,82.17) v1(0.76,80.9) v1(0.76,79.63) v1(0.76,78.36) v1(0.76,56.77) v1(0.76,55.5) v1(0.76,54.74) v1(0.76,53.21) v1(0.76,51.69) v1(0.76,49.91) v1(0.76,46.61) v1(0.76,45.34) v1(0.76,44.07) v1(0.76,42.8) v1(0.76,41.53) v1(0.76,40.26) v1(0.76,38.99) v1(0.76,37.72) v1(0.76,36.45) v1(0.76,27.56) v1(0.76,26.29) v1(0.76,25.02) v1(0.76,23.75) v1(0.76,22.48) v1(0.76,21.21) v1(0.76,19.94) v1(0.76,18.67) v1(0.76,17.4) v1(0.76,16.13) v1(0.76,14.86) v1(0.76,8.51) v1(0.76,7.24) v1(1.27,50.42) v1(1.3,46.48) v1(2.29,50.42) v1(2.41,53.59) v1(2.54,87.63) v1(3.27,56.01) v1(3.3,51.44) v1(3.81,89.53) v1(3.78,57.02) v1(3.84,46.53) v1(4.83,102.74) v1(5.87,53.37) v1(6.35,62.87) v1(6.38,46.53) v1(6.88,42.72) v1(6.88,41.45) v1(6.88,40.18) v1(7.13,0.76) v1(7.49,66.29) v1(7.49,64.39) v1(7.71,47.73) v1(7.72,14.71) v1(7.87,102.74) v1(7.95,44.05) v1(8.13,75.44) v1(8.42,14.72) v1(9.34,44.02) v1(9.6,67.16) v1(9.6,65.89) v1(9.67,0.76) v1(10.13,73.89) v1(10.16,75.44) v1(10.25,119.24) v1(10.48,54.86) v1(10.48,53.59) v1(10.48,52.32) v1(10.46,43.98) v1(11.66,42.06) v1(11.75,54.86) v1(11.75,53.59) v1(11.75,52.32) v1(11.85,43.95) v1(12.01,75.56) v1(12.06,72.62) v1(12.32,60.2) v1(12.45,103.63) v1(12.5,38.56) v1(12.57,46.81) v1(13.02,54.86) v1(13.02,53.59) v1(13.02,52.32) v1(13.21,60.2) v1(14.22,73.91) v1(14.22,59.69) v1(14.48,56.64) v1(15.04,46.53) v1(15.04,38.56) v1(15.33,119.24) v1(15.32,60.81) v1(16,56.52) v1(16,1.12) v1(16.6,119.24) v1(16.59,60.81) v1(17.27,1.12) v1(17.58,38.56) v1(17.87,119.24) v1(17.99,46.24) v1(18.08,59.54) v1(18.08,58.88) v1(18.54,1.12) v1(19,59.54) v1(19,58.88) v1(19.14,119.24) v1(19.63,48.77) v1(19.81,1.12) v1(19.86,59.54) v1(19.86,58.88) v1(20.41,119.24) v1(20.52,46.5) v1(20.57,81.15) v1(21.08,1.12) v1(21.34,51.18) v1(21.34,50.29) v1(21.68,119.24) v1(21.97,48.36) v1(22.35,1.12) v1(22.86,81.79) v1(22.95,119.24) v1(23.06,46.5) v1(23.62,1.12) v1(23.72,75.59) v1(24.13,81.79) v1(24.22,119.24) v1(24.31,78.36) v1(25.49,119.24) v1(26.06,75.59) v1(26.76,78.36) v1(27.05,47.01) v1(28.03,119.24) v1(29.3,119.24) v1(29.59,46.5) v1(30.48,50.77) v1(30.57,119.24) v1(30.61,54.02) v1(30.61,53.43) v1(31.12,50.77) v1(31.12,50.13) v1(31.24,54.02) v1(31.84,119.24) v1(31.75,50.13) v1(32.03,39.47) v1(32.03,38.46) v1(32.03,37.19) v1(32.77,42.11) v1(33.11,119.24) v1(33.25,51.58) v1(33.66,118.11) v1(34.04,42.11) v1(34.38,119.24) v1(34.96,84.86) v1(35.31,42.11) v1(35.49,21.01) v1(35.65,119.24) v1(35.94,42.11) v1(36.13,29.2) v1(36.2,118.11) v1(36.25,53.61) v1(36.25,51.58) v1(36.36,82.07) v1(36.58,42.11) v1(36.92,119.24) v1(37.13,29.25) v1(37.21,42.11) v1(37.75,82.07) v1(37.85,42.11) v1(38.19,119.24) v1(38.25,77.76) v1(38.3,29.14) v1(38.48,42.11) v1(39.12,42.11) v1(39.15,82.07) v1(39.46,119.24) v1(39.54,77.76) v1(39.65,29.16) v1(39.67,22.89) v1(39.75,42.11) v1(40.25,20.93) v1(40.39,42.11) v1(40.64,29.23) v1(40.73,119.24) v1(40.83,77.76) v1(41.66,59.56) v1(41.66,58.8) v1(41.94,82.07) v1(42,119.24) v1(42.11,77.76) v1(42.11,43.21) v1(42.25,51.58) v1(43.27,119.24) v1(43.4,77.76) v1(43.48,29.21) v1(43.75,51.58) v1(44.22,88.81) v1(44.35,91.73) v1(44.32,29.24) v1(44.54,119.24) v1(44.53,87.41) v1(44.69,77.76) v1(44.91,22) v1(44.93,21.01) v1(45.25,51.58) v1(45.81,119.24) v1(45.75,85.08) v1(45.97,77.76) v1(46.75,51.58) v1(46.79,32.36) v1(46.99,115.57) v1(47.08,119.24) v1(47.26,77.76) v1(48.01,91.73) v1(48.01,90.46) v1(48.01,87.41) v1(48.01,60.96) v1(48.26,115.57) v1(48.34,35.43) v1(48.34,34.8) v1(48.35,119.24) v1(48.85,25) v1(48.92,34.39) v1(49.04,0.76) v1(49.28,60.33) v1(49.28,59.56) v1(49.28,58.8) v1(49.53,115.57) v1(49.47,22.75) v1(49.62,119.24) v1(49.83,43.28) v1(49.76,35.36) v1(49.77,27.15) v1(50.01,114.94) v1(50.25,115.61) v1(50.31,0.76) v1(50.47,43.28) v1(50.83,22.39) v1(50.89,119.24) v1(51.33,22.39) v1(51.58,0.76) v1(51.84,22.39) v1(51.92,12.42) v1(52.16,119.24) v1(52.32,116.05) v1(52.32,24.97) v1(52.35,22.39) v1(52.4,30.07) v1(52.68,31.41) v1(52.7,22.99) v1(52.86,22.39) v1(52.85,0.76) v1(53.19,12.42) v1(53.43,119.24) v1(54.12,0.76) v1(54.25,34.16) v1(54.41,44.6) v1(54.46,12.42) v1(54.88,25.35) v1(54.99,58.17) v1(55.15,22.99) v1(55.37,11.99) v1(55.37,10.72) v1(55.37,9.45) v1(55.37,8.18) v1(55.37,6.91) v1(55.37,5.64) v1(55.37,4.37) v1(55.81,25.35) v1(56.52,90.55) v1(56.64,35.43) v1(56.64,34.16) v1(56.64,32.89) v1(57.02,61.59) v1(57.67,26.74) v1(57.78,90.55) v1(57.91,35.43) v1(57.91,34.16) v1(57.91,32.89) v1(57.91,17.81) v1(58.48,60.45) v1(58.48,58.17) v1(58.67,91.31) v1(58.7,41.66) v1(59.18,35.43) v1(59.18,34.16) v1(59.18,32.89) v1(59.33,43.71) v1(59.46,20.5) v1(59.46,19.86) v1(59.94,114.13) v1(59.88,26.74) v1(60.01,59.05) v1(61.06,43.71) v1(61.21,116.67) v1(61.21,115.4) v1(61.21,114.13) v1(62.05,25.58) v1(62.48,116.67) v1(62.78,43.71) v1(63.58,54.46) v1(64.01,16.03) v1(64.28,44.34) v1(64.49,93.14) v1(64.49,91.87) v1(64.49,90.6) v1(64.49,89.33) v1(64.86,119.24) v1(65.76,89.33) v1(65.91,27.2) v1(65.91,26.57) v1(66.13,119.24) v1(66.38,15.93) v1(67.03,89.33) v1(67.4,119.24) v1(67.5,59.08) v1(67.75,45.8) v1(68.3,89.33) v1(68.64,16.1) v1(68.67,119.24) v1(69,59.08) v1(69.24,16.1) v1(69.34,115.65) v1(69.47,97.54) v1(69.5,44.49) v1(69.72,88.65) v1(69.94,119.24) v1(70.74,97.54) v1(70.84,89.33) v1(70.76,25.15) v1(70.76,24.51) v1(70.76,23.88) v1(70.76,23.24) v1(70.76,22.61) v1(70.76,21.97) v1(70.99,95.25) v1(71.21,119.24) v1(71.3,118.26) v1(71.68,16.1) v1(71.88,96.95) v1(71.88,95.68) v1(71.88,94.41) v1(71.88,93.14) v1(71.88,91.87) v1(71.88,90.6) v1(71.88,89.33) v1(71.96,67.86) v1(71.96,65.41) v1(72,60.09) v1(72.11,116.84) v1(72.11,27.33) v1(72.25,45.84) v1(72.48,119.24) v1(72.72,118.26) v1(72.75,27.33) v1(73.17,0.76) v1(73.3,19.33) v1(73.3,18.75) v1(73.3,18.16) v1(73.45,67.86) v1(73.45,65.41) v1(73.75,45.84) v1(73.75,119.24) v1(73.99,116.46) v1(74.23,16.1) v1(74.44,0.76) v1(74.65,27.33) v1(75.02,119.24) v1(74.95,67.86) v1(74.95,65.41) v1(75,60.09) v1(75.25,52.58) v1(75.25,44.83) v1(75.71,0.76) v1(75.84,114.02) v1(75.84,111.79) v1(76.29,119.24) v1(76.5,60.09) v1(76.8,111.75) v1(76.98,0.76) v1(77.56,119.24) v1(78.23,80.77) v1(78.25,0.76) v1(78.83,119.24) v1(78.75,111.41) v1(79.22,21.69) v1(79.39,111.41) v1(79.39,110.77) v1(79.63,27.63) v1(79.7,45.47) v1(80.02,111.41) v1(80.02,110.77) v1(80.01,100.46) v1(80.01,99.19) v1(80.01,97.92) v1(80.01,92.84) v1(80.01,91.57) v1(80.01,90.3) v1(80.01,89.03) v1(80.1,119.24) v1(80.16,27.63) v1(80.64,27.86) v1(80.77,97.54) v1(80.95,96.01) v1(80.95,94.49) v1(81,22.48) v1(81.15,87.5) v1(81.15,27.86) v1(81.37,119.24) v1(81.79,90.55) v1(82.12,106.55) v1(82.42,87.5) v1(82.37,25.12) v1(82.37,23.85) v1(82.64,119.24) v1(82.88,106.55) v1(83.64,25.12) v1(83.64,23.85) v1(83.91,119.24) v1(84.2,78.49) v1(84.25,45.84) v1(84.51,83.74) v1(84.66,95.91) v1(84.89,112.04) v1(84.96,87.5) v1(85.14,85.41) v1(85.18,119.24) v1(85.39,98.12) v1(85.42,64.9) v1(85.75,45.84) v1(85.85,90.86) v1(85.98,111.51) v1(85.98,87.88) v1(86.09,18.07) v1(86.45,84.42) v1(86.45,82) v1(86.45,79.59) v1(86.4,77.17) v1(86.45,119.24) v1(86.74,107.7) v1(86.79,90.14) v1(87.02,99.44) v1(87.02,98.17) v1(87.02,96.9) v1(87.22,31.01) v1(87.22,30.38) v1(87.22,29.74) v1(87.25,45.84) v1(87.45,64.92) v1(87.42,36.25) v1(87.42,34.98) v1(87.5,107.7) v1(88.29,99.44) v1(88.29,98.17) v1(88.29,96.9) v1(88.27,89.51) v1(88.73,90.98) v1(88.75,45.84) v1(88.69,36.25) v1(88.69,34.98) v1(88.86,84.42) v1(88.86,79.59) v1(88.85,18.11) v1(88.99,119.24) v1(89.15,108.97) v1(89.42,88.2) v1(89.54,92.84) v1(89.48,64.92) v1(89.56,99.44) v1(89.56,98.17) v1(89.56,96.9) v1(89.57,68.61) v1(90.26,119.24) v1(90.78,72.02) v1(90.78,69.61) v1(90.89,18.07) v1(90.98,36.17) v1(91.07,92.58) v1(91.27,89.84) v1(91.53,119.24) v1(91.54,64.92) v1(91.61,36.17) v1(91.8,88.38) v1(91.8,85.97) v1(92.04,69.48) v1(92.25,36.17) v1(92.42,93.14) v1(92.8,119.24) v1(93,53.09) v1(93.31,72.07) v1(93.31,69.66) v1(93.46,91.03) v1(93.62,93.16) v1(93.56,64.92) v1(93.68,89.68) v1(93.65,18.11) v1(93.88,96.32) v1(93.88,94.86) v1(94.07,119.24) v1(94.08,81.49) v1(94.08,80.22) v1(94.08,78.95) v1(94.52,68.61) v1(94.5,53.09) v1(94.72,30.15) v1(94.72,29.51) v1(95.25,107.95) v1(95.34,119.24) v1(95.35,81.49) v1(95.35,78.95) v1(95.32,37.01) v1(95.32,36.37) v1(95.72,72.07) v1(95.72,69.66) v1(95.89,107.95) v1(96.04,93.16) v1(96,53.09) v1(96.03,0.76) v1(96.29,96.32) v1(96.29,94.86) v1(96.61,119.24) v1(96.62,81.49) v1(96.62,80.22) v1(96.62,78.95) v1(96.88,92.71) v1(96.93,68.61) v1(97.3,0.76) v1(97.54,89.53) v1(97.54,88.01) v1(97.5,53.09) v1(98.63,72.36) v1(99.15,119.24) v1(99.29,34.75) v1(99.29,34.16) v1(99.52,14.78) v1(99.9,72.36) v1(99.87,34.75) v1(99.87,34.16) v1(100.15,14.78) v1(100.33,102.87) v1(100.33,101.6) v1(100.33,100.46) v1(100.33,99.06) v1(100.33,97.79) v1(100.33,96.52) v1(100.28,19.02) v1(100.42,119.24) v1(100.91,19.02) v1(101.69,119.24) v1(101.9,14.15) v1(102.03,15.65) v1(102.07,8.56) v1(102.69,81.76) v1(102.69,81.13) v1(103.3,76.81) v1(104.23,119.24) v1(104.29,76.12) v1(104.28,8.53) v1(104.5,15.34) v1(105.39,18.18) v1(105.5,119.24) v1(105.94,76.2) v1(106.07,34.42) v1(106.26,18.97) v1(106.65,34.42) v1(106.77,119.24) v1(106.91,14.15) v1(106.98,8.63) v1(107.21,76.2) v1(107.19,18.97) v1(107.26,7.97) v1(108.04,119.24) v1(108.1,18.95) v1(108.1,18.18) v1(108.48,76.2) v1(108.56,9.4) v1(109.31,119.24) v1(109.45,14.15) v1(109.55,33.43) v1(110.08,36.8) v1(110.09,34.52) v1(110.13,33.43) v1(110.13,32.84) v1(110.58,119.24) v1(110.57,44.3) v1(110.57,43.03) v1(110.57,41.76) v1(110.57,40.49) v1(110.62,26.42) v1(110.62,25.4) v1(110.72,33.43) v1(110.72,32.84) v1(110.82,18.18) v1(110.86,18.97) v1(111.58,91.19) v1(112.22,91.19) v1(112.65,37.06) v1(112.65,34.26) v1(112.9,8.13) v1(113.61,86.51) v1(113.84,0.76) v1(115.11,0.76) v1(117.9,0.76) v1(118.8,35.39) v1(118.83,33.89) v1(118.83,32.39) v1(118.85,30.89) v1(119.17,0.76) v1(119.68,19.53) v1(119.68,18.9) v1(119.68,18.26) v1(120.09,25.25) v1(120.44,0.76) v1(121.28,22.25) v1(121.28,21.62) v1(121.92,22.25) v1(121.92,21.62) v1(122.63,25.25) v1(123.01,44.55) v1(123.24,0.76) v1(123.6,109.18) v1(123.6,108.55) v1(123.6,107.91) v1(123.7,42.92) v1(123.95,40.34) v1(123.95,37.34) v1(124.32,31.42) v1(124.46,28.83) v1(124.51,0.76) v1(124.97,37.97) v1(125.32,30.18) v1(125.78,0.76) v1(126.02,42.92) v1(127.05,0.76) v1(134.24,58.56) v1(134.24,57.29) v1(134.24,56.02) v1(134.24,29.35) v1(134.24,28.08) v1(134.24,26.81) v1(134.24,25.54) v1(134.24,24.27) v1(134.24,23) v1(134.24,21.73) v1(134.24,20.46) v1(134.24,19.19) v1(134.24,17.92) v1(134.24,16.65) v1(134.24,15.38) v1(134.24,14.11) v1(134.24,12.84) v1(134.24,11.57) v1(134.24,10.3) v1(134.24,9.03) v1(134.24,7.76)
